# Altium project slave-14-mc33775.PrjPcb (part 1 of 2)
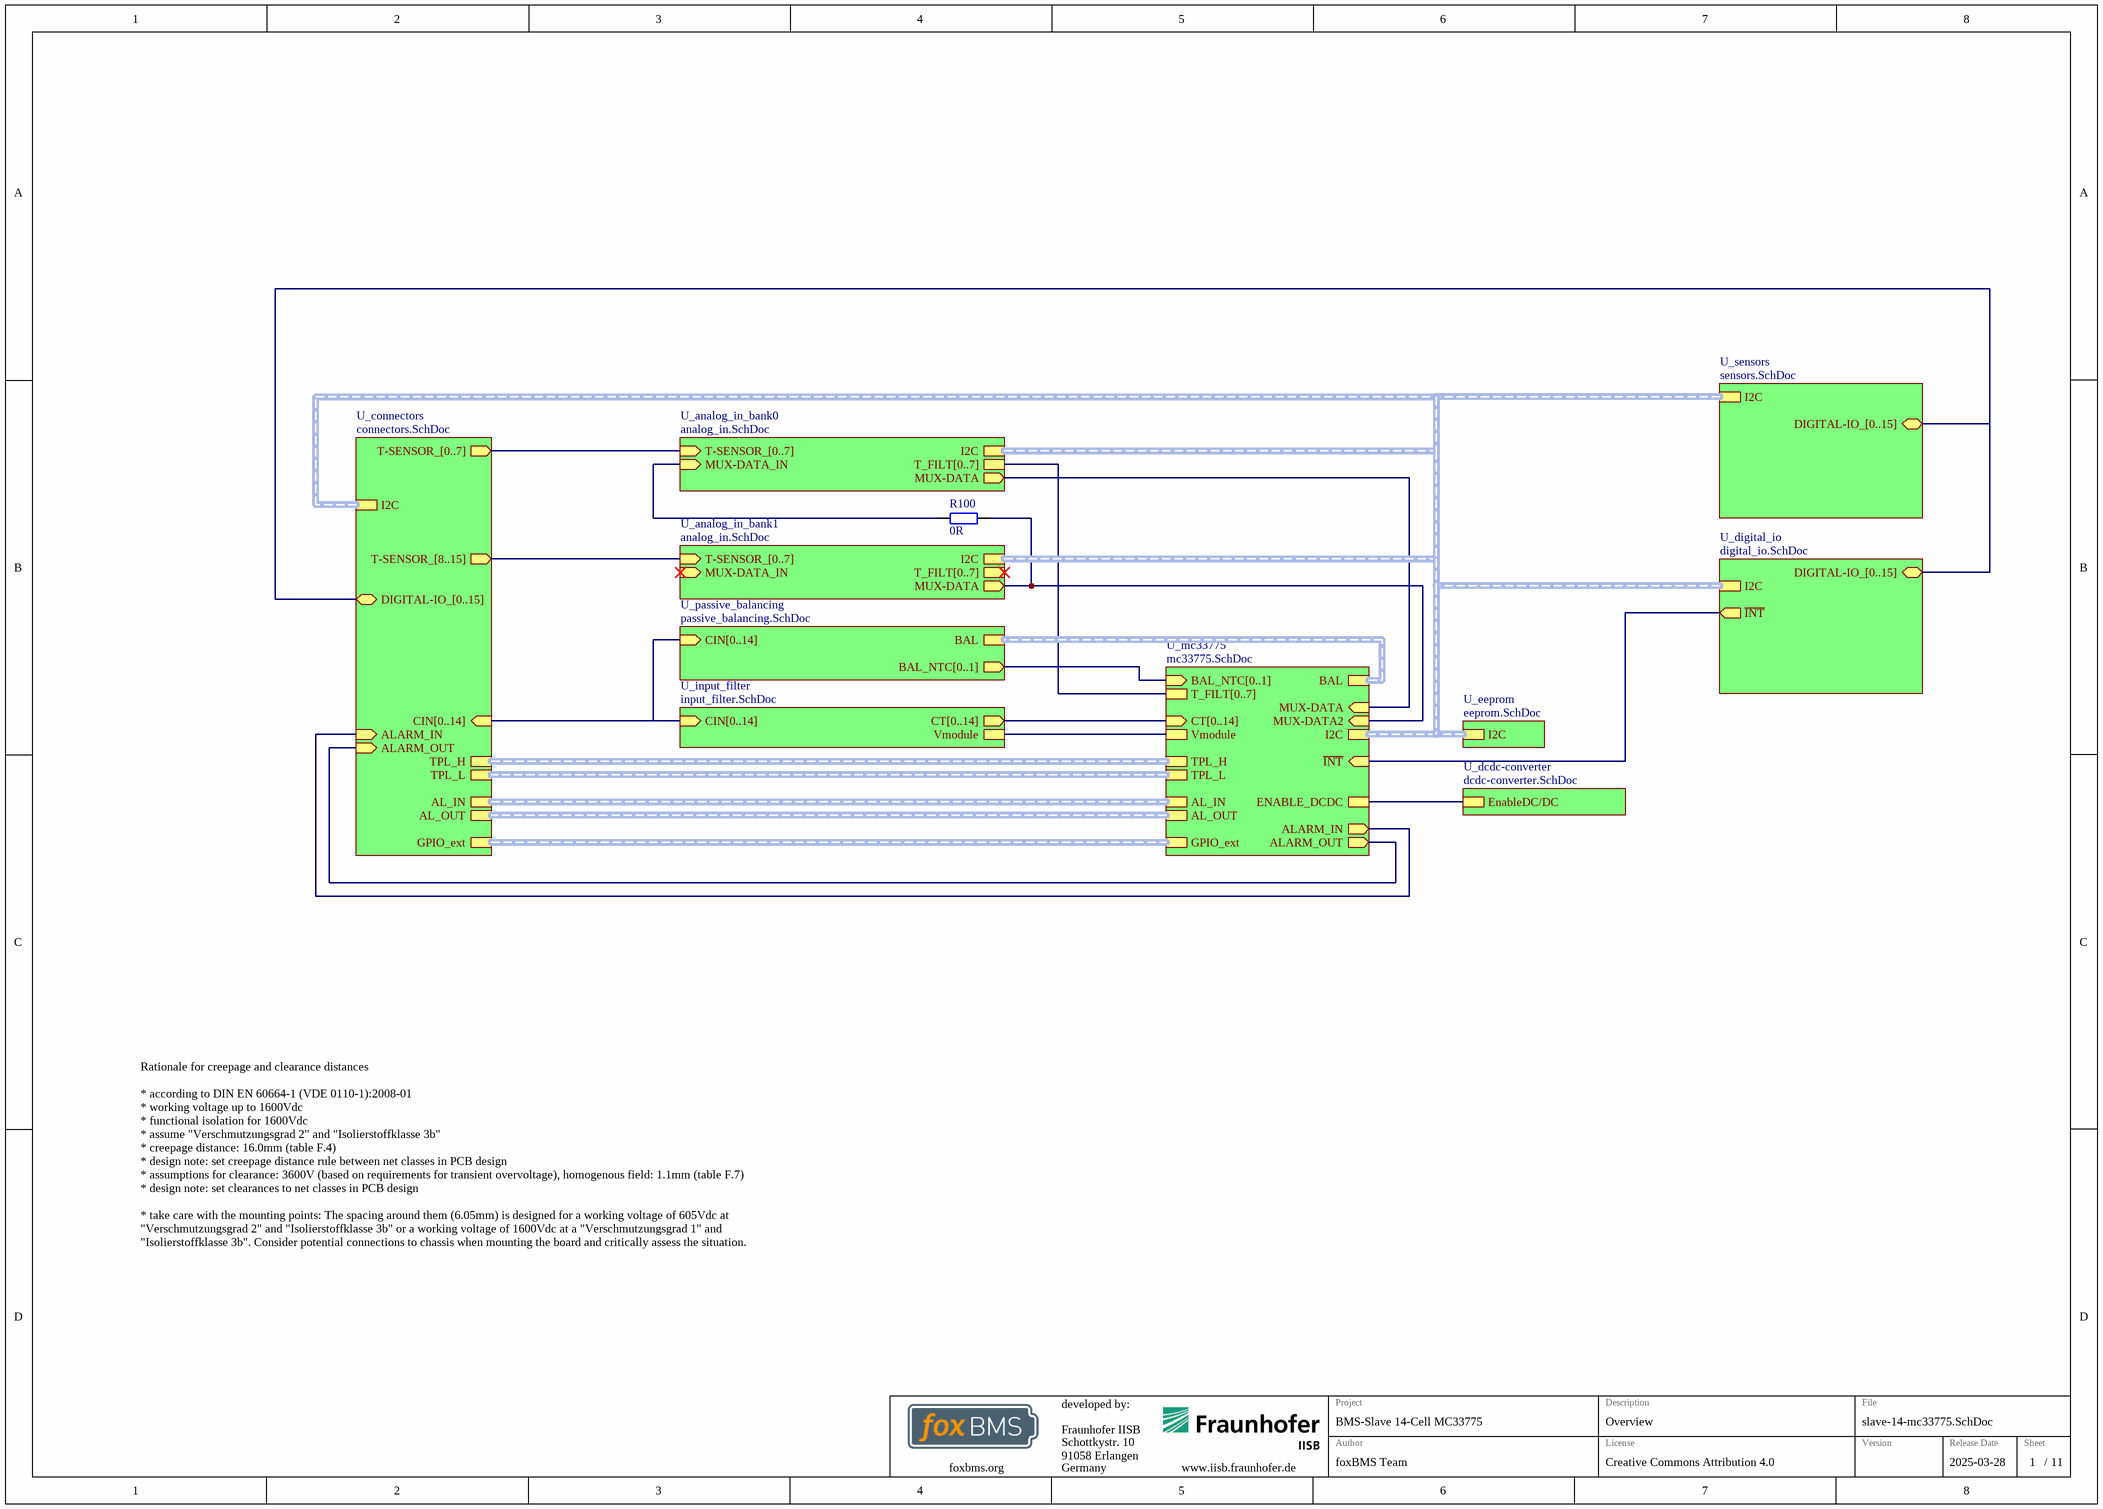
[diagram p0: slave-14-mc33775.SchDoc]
Global_Suffix_Version: 0; Global_Major_Minor_Patch_Version: 1.0.3; GlobalVersion: ='v'+Global_Major_Minor_Patch_Version+'-'+Global_Suffix_Version; GlobalStatus: A; GlobalProject: BMS-Slave 14-Cell MC33775; GlobalLicense: Creative Commons Attribution 4.0; GlobalDate: 2025-03-28; GlobalAuthor: foxBMS Team
11 sheets, 421 parts. Net scope: hierarchical (ports join the sheet entries above them; power ports are global).
Board file: slave-14-mc33775.PcbDoc
Sheets:
  slave-14-mc33775.SchDoc
    U_mc33775 = mc33775.SchDoc
      U_ldo = ldo.SchDoc
    U_eeprom = eeprom.SchDoc
    U_input_filter = input_filter.SchDoc
    U_passive_balancing = passive_balancing.SchDoc
    U_analog_in_bank0 = analog_in.SchDoc
    U_connectors = connectors.SchDoc
    U_dcdc-converter = dcdc-converter.SchDoc
    U_sensors = sensors.SchDoc
    U_digital_io = digital_io.SchDoc
    U_analog_in_bank1 = analog_in.SchDoc

## Sheet slave-14-mc33775.SchDoc
size A3; DocumentNumber: 1; SheetNumber: 1; SheetTotal: 11; SheetDescription: Overview

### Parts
R100  0R  [RESC1608X05N]

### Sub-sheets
U_analog_in_bank0 = analog_in.SchDoc: MUX-DATA (out), T-SENSOR_[0..7] (in), I2C (harness I2C), MUX-DATA_IN (in), T_FILT[0..7]
U_analog_in_bank1 = analog_in.SchDoc: MUX-DATA (out), T-SENSOR_[0..7] (in), I2C (harness I2C), MUX-DATA_IN (in), T_FILT[0..7]
U_connectors = connectors.SchDoc: T-SENSOR_[0..7] (out), CIN[0..14] (in), TPL_L (harness TPL), TPL_H (harness TPL), AL_OUT (harness ALARM), AL_IN (harness ALARM), GPIO_ext (harness GPIO_ext), T-SENSOR_[8..15] (out), DIGITAL-IO_[0..15] (bidir), ALARM_IN (in), ALARM_OUT (in), I2C (harness I2C)
U_dcdc-converter = dcdc-converter.SchDoc: EnableDC/DC
U_digital_io = digital_io.SchDoc: DIGITAL-IO_[0..15] (bidir), ~{INT} (out), I2C (harness I2C)
U_eeprom = eeprom.SchDoc: I2C (harness I2C)
U_input_filter = input_filter.SchDoc: CT[0..14] (out), CIN[0..14] (in), Vmodule
U_mc33775 = mc33775.SchDoc: I2C (harness I2C), CT[0..14] (in), BAL (harness BAL), AL_IN (harness ALARM), AL_OUT (harness ALARM), BAL_NTC[0..1] (in), MUX-DATA (in), TPL_L (harness TPL), TPL_H (harness TPL), GPIO_ext (harness GPIO_ext), MUX-DATA2 (in), ~{INT} (in), T_FILT[0..7], ENABLE_DCDC, ALARM_IN (out), ALARM_OUT (out), Vmodule
U_passive_balancing = passive_balancing.SchDoc: CIN[0..14] (in), BAL (harness BAL), BAL_NTC[0..1] (out)
U_sensors = sensors.SchDoc: DIGITAL-IO_[0..15] (bidir), I2C (harness I2C)

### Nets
VMODULE: sheet U_mc33775/Vmodule, sheet U_input_filter/Vmodule
ALARM_IN: sheet U_mc33775/ALARM_IN, sheet U_connectors/ALARM_IN
ALARM_OUT: sheet U_mc33775/ALARM_OUT, sheet U_connectors/ALARM_OUT
INT: sheet U_mc33775/~{INT}, sheet U_digital_io/~{INT}
MUX-DATA_IN: R100.1 ; sheet U_analog_in_bank0/MUX-DATA_IN
MUX_DATA: sheet U_mc33775/MUX-DATA, sheet U_analog_in_bank0/MUX-DATA
MUX_DATA2: R100.2 ; sheet U_mc33775/MUX-DATA2, sheet U_analog_in_bank1/MUX-DATA
NetR601_2: sheet U_mc33775/ENABLE_DCDC, sheet U_dcdc-converter/EnableDC/DC

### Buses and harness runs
bus sheet U_analog_in_bank0/T-SENSOR_[0..7] = sheet U_connectors/T-SENSOR_[0..7]
bus sheet U_analog_in_bank0/T_FILT[0..7] = sheet U_mc33775/T_FILT[0..7]
bus sheet U_analog_in_bank1/T-SENSOR_[0..7] = sheet U_connectors/T-SENSOR_[8..15]
bus sheet U_connectors/CIN[0..14] = sheet U_input_filter/CIN[0..14] = sheet U_passive_balancing/CIN[0..14]
bus sheet U_connectors/DIGITAL-IO_[0..15] = sheet U_digital_io/DIGITAL-IO_[0..15] = sheet U_sensors/DIGITAL-IO_[0..15]
bus sheet U_input_filter/CT[0..14] = sheet U_mc33775/CT[0..14]
bus sheet U_mc33775/BAL_NTC[0..1] = sheet U_passive_balancing/BAL_NTC[0..1]
harness sheet U_analog_in_bank0/I2C = sheet U_analog_in_bank1/I2C = sheet U_connectors/I2C = sheet U_digital_io/I2C = sheet U_eeprom/I2C = sheet U_mc33775/I2C = sheet U_sensors/I2C
harness sheet U_connectors/AL_IN = sheet U_mc33775/AL_IN
harness sheet U_connectors/AL_OUT = sheet U_mc33775/AL_OUT
harness sheet U_connectors/GPIO_ext = sheet U_mc33775/GPIO_ext
harness sheet U_connectors/TPL_H = sheet U_mc33775/TPL_H
harness sheet U_connectors/TPL_L = sheet U_mc33775/TPL_L
harness sheet U_mc33775/BAL = sheet U_passive_balancing/BAL

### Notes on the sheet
- Rationale for creepage and clearance distances
  * according to DIN EN 60664-1 (VDE 0110-1):2008-01
  * working voltage up to 1600Vdc
  * functional isolation for 1600Vdc
  * assume "Verschmutzungsgrad 2" and "Isolierstoffklasse 3b"
  * creepage distance: 16.0mm (table F.4)
  * design note: set creepage distance rule between net classes in PCB design
  * assumptions for clearance: 3600V (based on requirements for transient overvoltage), homogenous field: 1.1mm (table F.7)
  * design note: set clearances to net classes in PCB design
  * take care with the mounting points: The spacing around them (6.05mm) is designed for a working voltage of 605Vdc at "Verschmutzungsgrad 2" and "Isolierstoffklasse 3b" or a working voltage of 1600Vdc at a "Verschmutzungsgrad 1" and "Isolierstoffklasse 3b". Consider potential connections to chassis when mounting the board and critically assess the situation.

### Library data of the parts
R100 = gen_R_0R_0603: SMD Resistor 0R 0603; Power: 0.1W; Case EIA: 0603; Case Metric: 1608; Maximum Working Voltage: 75V; PnP Package: 0603R; Automotive Qualified: True; PnP equipped: x

## Sheet mc33775.SchDoc
size A3; DocumentNumber: 2; SheetNumber: 2; SheetTotal: 11; SheetDescription: MC33775A BMS IC
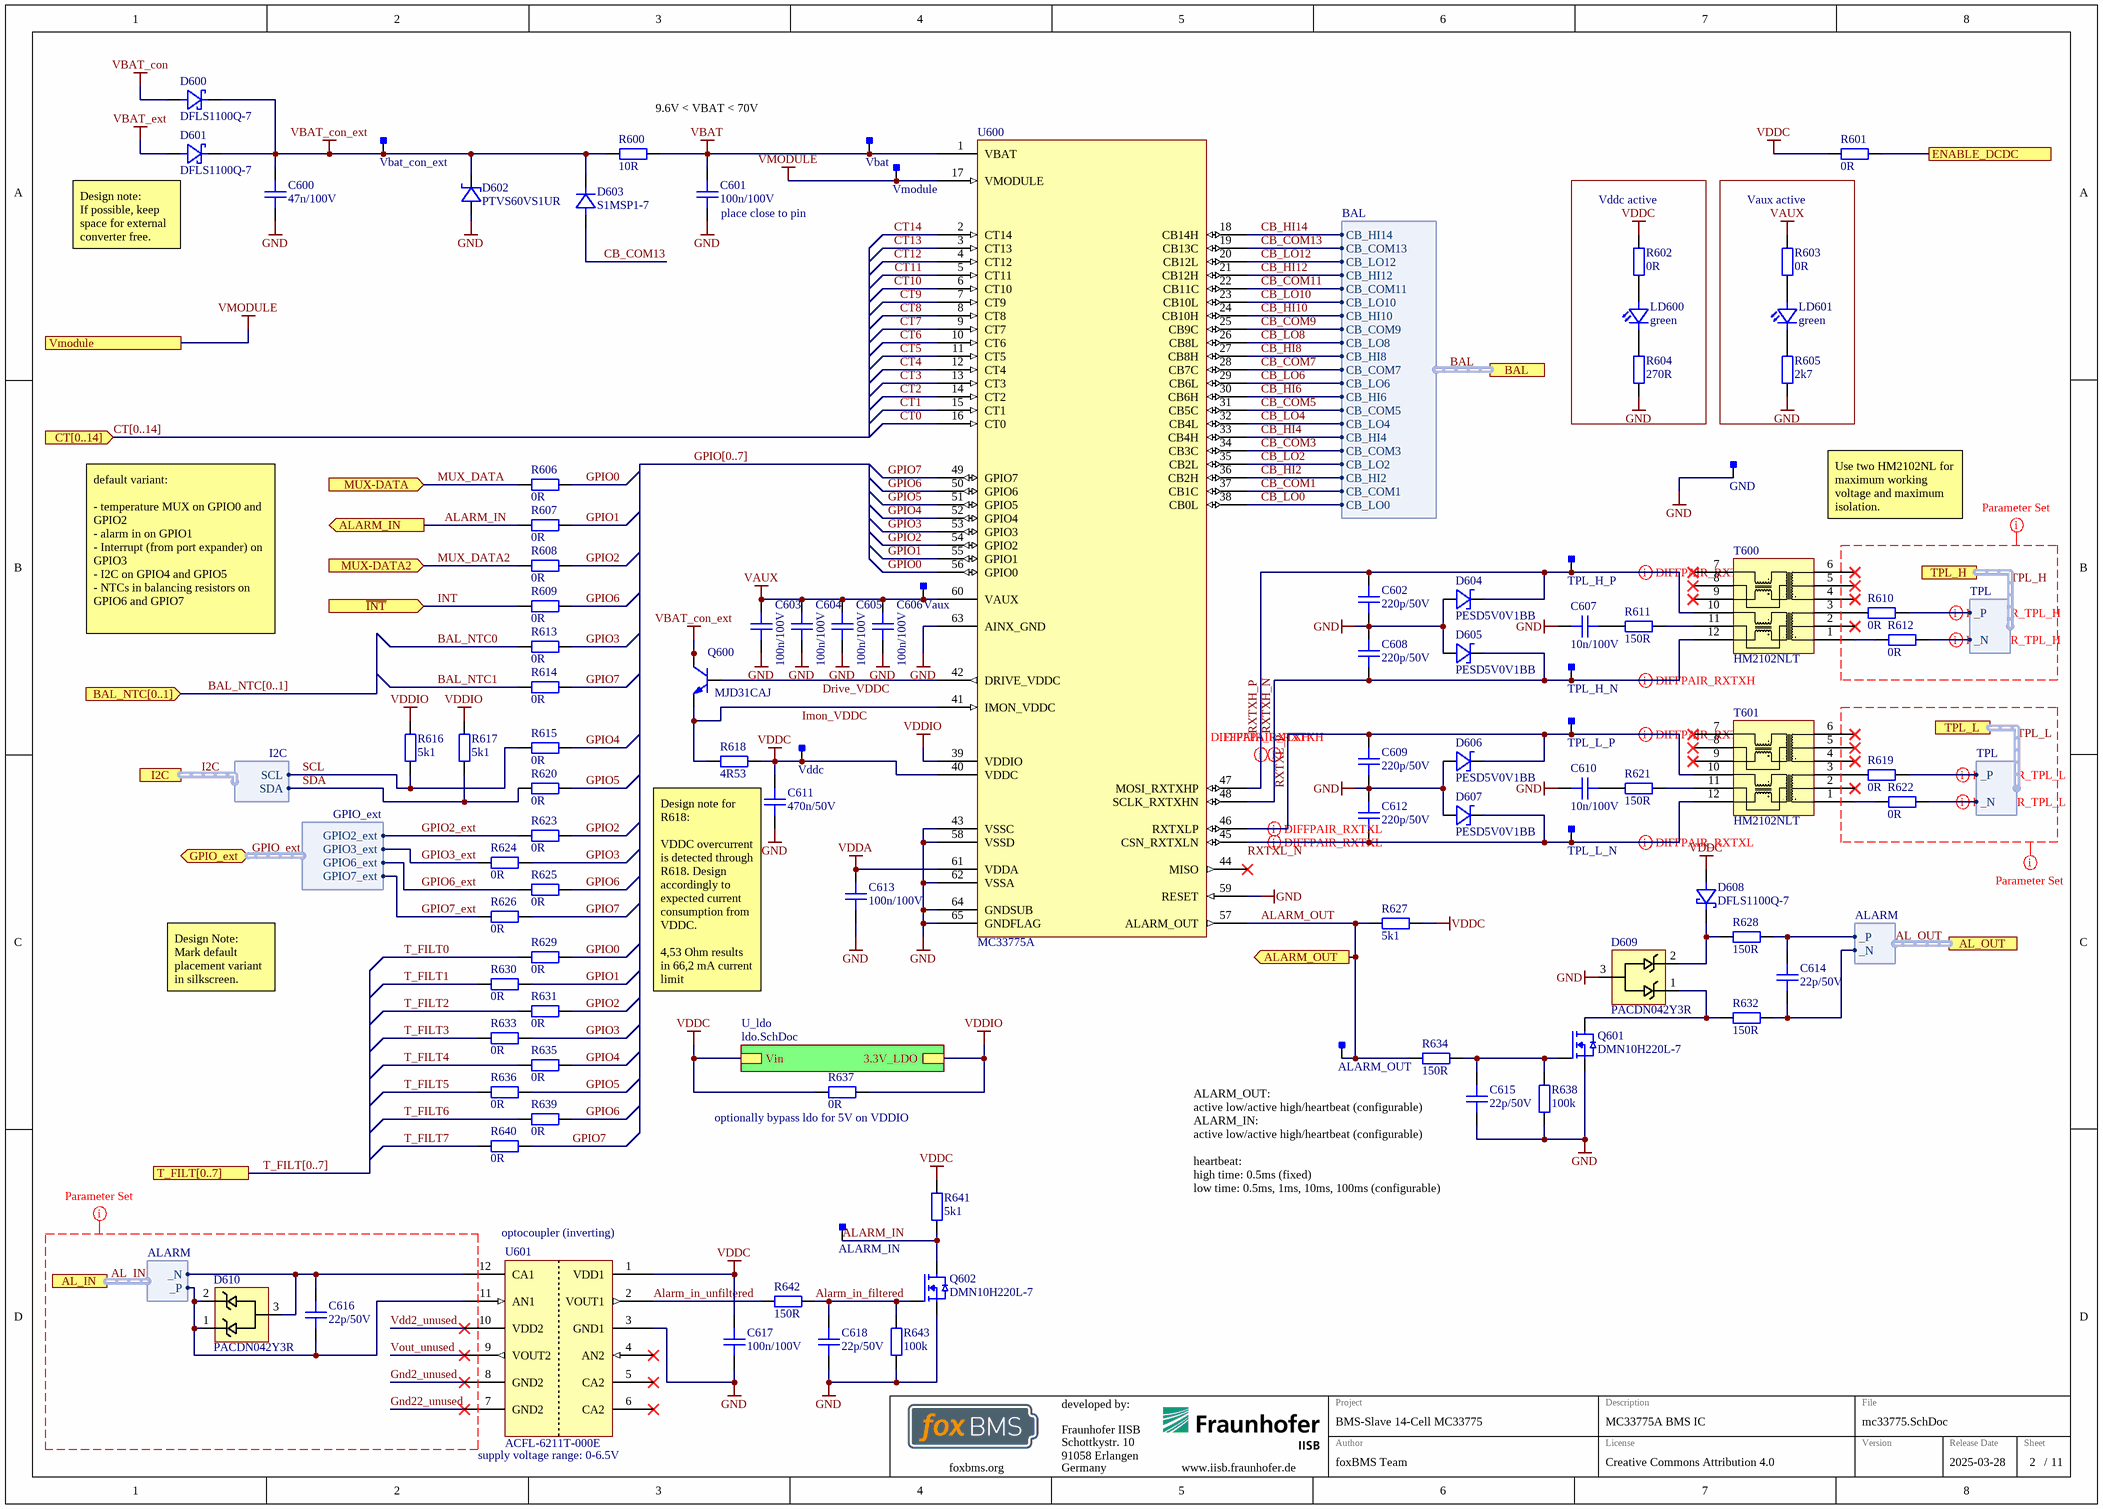
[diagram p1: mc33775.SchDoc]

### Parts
ALARM_IN  Testpoint_Square  [Testpoint_S1]  (value not drawn)  (no BOM)
ALARM_OUT  Testpoint_Square  [Testpoint_S1]  (value not drawn)  (no BOM)
C600  47n/100V  [CAPC1608X08N]
C601  100n/100V  [CAPC1608X08N]
C602  220p/50V  [CAPC1608X08N]
C603  100n/100V  [CAPC1608X08N]
C604  100n/100V  [CAPC1608X08N]
C605  100n/100V  [CAPC1608X08N]
C606  100n/100V  [CAPC1608X08N]
C607  10n/100V  [CAPC1608X08N]
C608  220p/50V  [CAPC1608X08N]
C609  220p/50V  [CAPC1608X08N]
C610  10n/100V  [CAPC1608X08N]
C611  470n/50V  [CAPC1608X08N]
C612  220p/50V  [CAPC1608X08N]
C613  100n/100V  [CAPC1608X08N]
C614  22p/50V  [CAPC1005X06N]
C615  22p/50V  [CAPC1005X06N]
C616  22p/50V  [CAPC1005X06N]
C617  100n/100V  [CAPC1608X08N]
C618  22p/50V  [CAPC1005X06N]
D600  DFLS1100Q-7  [PowerDI123]
D601  DFLS1100Q-7  [PowerDI123]
D602  PTVS60VS1UR  [NEXPERIA_PTVSxS1UR]
D603  S1MSP1-7  [S1MSP1]
D604  PESD5V0V1BB  [SOD523_PESD_NEXPERIA]
D605  PESD5V0V1BB  [SOD523_PESD_NEXPERIA]
D606  PESD5V0V1BB  [SOD523_PESD_NEXPERIA]
D607  PESD5V0V1BB  [SOD523_PESD_NEXPERIA]
D608  DFLS1100Q-7  [PowerDI123]
D609  PACDN042Y3R  [ON-SEMI-SOT-23-3-CASE-318-08]
D610  PACDN042Y3R  [ON-SEMI-SOT-23-3-CASE-318-08]
GND  Testpoint_Square  [Testpoint_S1]  (value not drawn)  (no BOM)
LD600  green  [LEDC1608X07N]
LD601  green  [LEDC1608X07N]
Q600  MJD31CAJ  [NEXPERIA_DPAK_SOT428C]
Q601  DMN10H220L-7  [SOT95P237X110-3N]
Q602  DMN10H220L-7  [SOT95P237X110-3N]
R600  10R  [RESC2012X05N]
R601  0R  [RESC1608X05N]
R602  0R  [RESC1608X05N]
R603  0R  [RESC1608X05N]
R604  270R  [RESC1608X05N]
R605  2k7  [RESC1608X05N]
R606  0R  [RESC1608X05N]
R607  0R  [RESC1608X05N]
R608  0R  [RESC1608X05N]
R609  0R  [RESC1608X05N]
R610  0R  [RESC1608X05N]
R611  150R  [RESC1608X05N]
R612  0R  [RESC1608X05N]
R613  0R  [RESC1608X05N]
R614  0R  [RESC1608X05N]
R615  0R  [RESC1608X05N]
R616  5k1  [RESC1608X05N]
R617  5k1  [RESC1608X05N]
R618  4R53  [RESC1608X05N]
R619  0R  [RESC1608X05N]
R620  0R  [RESC1608X05N]
R621  150R  [RESC1608X05N]
R622  0R  [RESC1608X05N]
R623  0R  [RESC1608X05N]
R624  0R  [RESC1608X05N]
R625  0R  [RESC1608X05N]
R626  0R  [RESC1608X05N]
R627  5k1  [RESC1608X05N]
R628  150R  [RESC1608X05N]
R629  0R  [RESC1608X05N]
R630  0R  [RESC1608X05N]
R631  0R  [RESC1608X05N]
R632  150R  [RESC1608X05N]
R633  0R  [RESC1608X05N]
R634  150R  [RESC1608X05N]
R635  0R  [RESC1608X05N]
R636  0R  [RESC1608X05N]
R637  0R  [RESC1608X05N]
R638  100k  [RESC1608X05N]
R639  0R  [RESC1608X05N]
R640  0R  [RESC1608X05N]
R641  5k1  [RESC1608X05N]
R642  150R  [RESC1608X05N]
R643  100k  [RESC1608X05N]
T600  HM2102NLT  [HM2102NL]
T601  HM2102NLT  [HM2102NL]
TPL_H_N  Testpoint_Square  [Testpoint_S1]  (value not drawn)  (no BOM)
TPL_H_P  Testpoint_Square  [Testpoint_S1]  (value not drawn)  (no BOM)
TPL_L_N  Testpoint_Square  [Testpoint_S1]  (value not drawn)  (no BOM)
TPL_L_P  Testpoint_Square  [Testpoint_S1]  (value not drawn)  (no BOM)
U600  MC33775A  [NXP_SOT1510-2]
U601  ACFL-6211T-000E  [Broadcom_ACFL-6211T]
Vaux  Testpoint_Square  [Testpoint_S1]  (value not drawn)  (no BOM)
Vbat  Testpoint_Square  [Testpoint_S1]  (value not drawn)  (no BOM)
Vbat_con_ext  Testpoint_Square  [Testpoint_S1]  (value not drawn)  (no BOM)
Vddc  Testpoint_Square  [Testpoint_S1]  (value not drawn)  (no BOM)
Vmodule  Testpoint_Square  [Testpoint_S1]  (value not drawn)  (no BOM)

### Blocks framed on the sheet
Vddc active: LD600 R602 R604
Vaux active: LD601 R603 R605

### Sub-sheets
U_ldo = ldo.SchDoc: 3.3V_LDO, Vin

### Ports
AL_IN (harness ALARM), AL_OUT (harness ALARM), ALARM_IN (out), ALARM_OUT (out), BAL (harness BAL), BAL_NTC[0..1] (in), CT[0..14] (in), ENABLE_DCDC, GPIO_ext (bidir, harness GPIO_ext), I2C (harness I2C), MUX-DATA2 (in), MUX-DATA (in), T_FILT[0..7], TPL_H (harness TPL), TPL_L (harness TPL), Vmodule, ~{INT} (in)

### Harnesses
BAL: CB_HI14, CB_COM13, CB_LO12, CB_HI12, CB_COM11, CB_LO10, CB_HI10, CB_COM9, CB_LO8, CB_HI8, CB_COM7, CB_LO6, CB_HI6, CB_COM5, CB_LO4, CB_HI4, CB_COM3, CB_LO2, CB_HI2, CB_COM1, CB_LO0
TPL: _P, _N
ALARM: _P, _N
I2C: SCL, SDA
GPIO_ext: GPIO3_ext, GPIO2_ext, GPIO6_ext, GPIO7_ext

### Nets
GND: C600.1 C601.1 C602.1 C603.1 C604.1 C605.1 C606.1 C607.1 C608.2 C609.1 C610.1 C611.1 C612.2 C613.1 C615.1 C617.1 C618.1 D602.2(A) D604.2(A) D605.2(A) D606.2(A) D607.2(A) D609.3 GND.1 Q601.S Q602.S R604.1 R605.1 R638.2 R643.2 U600.43(VSSC) U600.58(VSSD) U600.59(RESET) U600.62(VSSA) U600.63(AINX_GND) U600.64(GNDSUB) U600.65(GNDFLAG) U601.3(GND1)
VAUX: C603.2 C604.2 C605.2 C606.2 R603.2 U600.60(VAUX) Vaux.1
VBAT: C601.2 R600.1 U600.1(VBAT) Vbat.1
VBAT_con: D600.2(A)
VBAT_con_ext: C600.2 D600.1(K) D601.1(K) D602.1(C) D603.1(K) Q600.2(C) Q600.4(C) R600.2 Vbat_con_ext.1
VBAT_ext: D601.2(A)
VDDA: C613.2 U600.61(VDDA)
VDDC: C611.2 C617.2 D608.2(A) R601.1 R602.2 R618.2 R627.1 R637.2 R641.1 U600.40(VDDC) U601.1(VDD1) Vddc.1 ; sheet U_ldo/Vin
VDDIO: R616.2 R617.2 R637.1 U600.39(VDDIO) ; sheet U_ldo/3.3V_LDO
VMODULE: U600.17(VMODULE) Vmodule.1 ; port Vmodule
AL_IN._N: C616.2 D610.3 U601.12(CA1) ; port AL_IN._N
AL_IN._P: C616.1 D610.1 D610.2 U601.11(AN1) ; port AL_IN._P
AL_OUT._N: C614.1 R632.2 ; port AL_OUT._N
AL_OUT._P: C614.2 R628.2 ; port AL_OUT._P
ALARM_IN: ALARM_IN.1 Q602.D R607.1 R641.2 ; port ALARM_IN
Alarm_in_filtered: C618.2 Q602.G R642.2 R643.1
Alarm_in_unfiltered: R642.1 U601.2(VOUT1)
ALARM_OUT: ALARM_OUT.1 R627.2 R634.1 U600.57(ALARM_OUT) ; port ALARM_OUT
BAL_NTC0: R613.1
BAL_NTC1: R614.1
CB_COM1: U600.37(CB1C) ; port BAL.CB_COM1  [project net BAL.CB_COM1]
CB_COM3: U600.34(CB3C) ; port BAL.CB_COM3  [project net BAL.CB_COM3]
CB_COM5: U600.31(CB5C) ; port BAL.CB_COM5  [project net BAL.CB_COM5]
CB_COM7: U600.28(CB7C) ; port BAL.CB_COM7  [project net BAL.CB_COM7]
CB_COM9: U600.25(CB9C) ; port BAL.CB_COM9  [project net BAL.CB_COM9]
CB_COM11: U600.22(CB11C) ; port BAL.CB_COM11  [project net BAL.CB_COM11]
CB_COM13: D603.2(A) U600.19(CB13C) ; port BAL.CB_COM13  [project net BAL.CB_COM13]
CB_HI2: U600.36(CB2H) ; port BAL.CB_HI2  [project net BAL.CB_HI2]
CB_HI4: U600.33(CB4H) ; port BAL.CB_HI4  [project net BAL.CB_HI4]
CB_HI6: U600.30(CB6H) ; port BAL.CB_HI6  [project net BAL.CB_HI6]
CB_HI8: U600.27(CB8H) ; port BAL.CB_HI8  [project net BAL.CB_HI8]
CB_HI10: U600.24(CB10H) ; port BAL.CB_HI10  [project net BAL.CB_HI10]
CB_HI12: U600.21(CB12H) ; port BAL.CB_HI12  [project net BAL.CB_HI12]
CB_HI14: U600.18(CB14H) ; port BAL.CB_HI14  [project net BAL.CB_HI14]
CB_LO0: U600.38(CB0L) ; port BAL.CB_LO0  [project net BAL.CB_LO0]
CB_LO2: U600.35(CB2L) ; port BAL.CB_LO2  [project net BAL.CB_LO2]
CB_LO4: U600.32(CB4L) ; port BAL.CB_LO4  [project net BAL.CB_LO4]
CB_LO6: U600.29(CB6L) ; port BAL.CB_LO6  [project net BAL.CB_LO6]
CB_LO8: U600.26(CB8L) ; port BAL.CB_LO8  [project net BAL.CB_LO8]
CB_LO10: U600.23(CB10L) ; port BAL.CB_LO10  [project net BAL.CB_LO10]
CB_LO12: U600.20(CB12L) ; port BAL.CB_LO12  [project net BAL.CB_LO12]
CT0: U600.16(CT0)
CT1: U600.15(CT1)
CT2: U600.14(CT2)
CT3: U600.13(CT3)
CT4: U600.12(CT4)
CT5: U600.11(CT5)
CT6: U600.10(CT6)
CT7: U600.9(CT7)
CT8: U600.8(CT8)
CT9: U600.7(CT9)
CT10: U600.6(CT10)
CT11: U600.5(CT11)
CT12: U600.4(CT12)
CT13: U600.3(CT13)
CT14: U600.2(CT14)
Drive_VDDC: Q600.1(B) U600.42(DRIVE_VDDC)
Gnd2_unused: U601.8(GND2)
Gnd22_unused: U601.7(GND2)
GPIO0: R606.2 R629.2 U600.56(GPIO0)
GPIO1: R607.2 R630.2 U600.55(GPIO1)
GPIO2: R608.2 R623.2 R631.2 U600.54(GPIO2)
GPIO2_ext: R623.1 ; port GPIO_ext.GPIO2_ext
GPIO3: R613.2 R624.2 R633.2 U600.53(GPIO3)
GPIO3_ext: R624.1 ; port GPIO_ext.GPIO3_ext
GPIO4: R615.2 R635.2 U600.52(GPIO4)
GPIO5: R620.2 R636.2 U600.51(GPIO5)
GPIO6: R609.2 R625.2 R639.2 U600.50(GPIO6)
GPIO6_ext: R625.1 ; port GPIO_ext.GPIO6_ext
GPIO7: R614.2 R626.2 R640.2 U600.49(GPIO7)
GPIO7_ext: R626.1 ; port GPIO_ext.GPIO7_ext
Imon_VDDC: Q600.3(E) R618.1 U600.41(IMON_VDDC)
INT: R609.1 ; port ~{INT}
MUX_DATA: R606.1 ; port MUX-DATA
MUX_DATA2: R608.1 ; port MUX-DATA2
RXTXH_N: C608.1 D605.1(C) T600.12 TPL_H_N.1 U600.48(SCLK_RXTXHN)
RXTXH_P: C602.2 D604.1(C) T600.10 TPL_H_P.1 U600.47(MOSI_RXTXHP)
RXTXL_N: C612.1 D607.1(C) T601.12 TPL_L_N.1 U600.45(CSN_RXTXLN)
RXTXL_P: C609.2 D606.1(C) T601.10 TPL_L_P.1 U600.46(RXTXLP)
SCL: R615.1 R616.1 ; port I2C.SCL  [project net I2C.SCL]
SDA: R617.1 R620.1 ; port I2C.SDA  [project net I2C.SDA]
T_FILT0: R629.1
T_FILT1: R630.1
T_FILT2: R631.1
T_FILT3: R633.1
T_FILT4: R635.1
T_FILT5: R636.1
T_FILT6: R639.1
T_FILT7: R640.1
TPL_H._N: R612.2 ; port TPL_H._N
TPL_H._P: R610.2 ; port TPL_H._P
TPL_L._N: R622.2 ; port TPL_L._N
TPL_L._P: R619.2 ; port TPL_L._P
Vdd2_unused: U601.10(VDD2)
Vout_unused: U601.9(VOUT2)
NetC607_2: C607.2 R611.1
NetC610_2: C610.2 R621.1
NetC615_2: C615.2 Q601.G R634.2 R638.1
NetD608_1: D608.1(K) D609.2 R628.1
NetD609_1: D609.1 Q601.D R632.1
NetLD600_1: LD600.1(C) R604.2
NetLD600_2: LD600.2(A) R602.1
NetLD601_1: LD601.1(C) R605.2
NetLD601_2: LD601.2(A) R603.1
NetR601_2: R601.2 ; port ENABLE_DCDC
NetR610_1: R610.1 T600.3
NetR611_2: R611.2 T600.11
NetR612_1: R612.1 T600.1
NetR619_1: R619.1 T601.3
NetR621_2: R621.2 T601.11
NetR622_1: R622.1 T601.1

Not connected (* = marked no-connect by the designer): T600 2* 4* 5* 6* 7* 8* 9*; T601 2* 4* 5* 6* 7* 8* 9*; U600 44(MISO)*; U601 4(AN2)* 5(CA2)* 6(CA2)*

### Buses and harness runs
bus BAL_NTC[0..1] = port BAL_NTC[0..1]
bus CT[0..14] = port CT[0..14]
bus GPIO[0..7]
bus T_FILT[0..7] = port T_FILT[0..7]
harness AL_IN = port AL_IN
harness AL_OUT = port AL_OUT
harness BAL = port BAL
harness GPIO_ext = port GPIO_ext
harness I2C = port I2C
harness TPL_H = port TPL_H
harness TPL_L = port TPL_L

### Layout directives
differential pair: RXTXH_N, RXTXH_P, RXTXL_N, RXTXL_P, TPL_L._N, TPL_L._P
differential pair; differential pair class TPL_H: TPL_H._N, TPL_H._P
net class TPL_high: TPL_H
net class TPL_low: TPL_L
net class ALARM_in: AL_IN, Gnd2_unused, Gnd22_unused, Vdd2_unused, Vout_unused

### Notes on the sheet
- (near R600) 9.6V < VBAT < 70V
- (near D601) Design note:
  If possible, keep space for external converter free.
- (near C601) place close to pin
- Use two HM2102NL for maximum working voltage and maximum isolation.
- default variant:
  - temperature MUX on GPIO0 and GPIO2
  - alarm in on GPIO1
  - Interrupt (from port expander) on GPIO3
  - I2C on GPIO4 and GPIO5
  - NTCs in balancing resistors on GPIO6 and GPIO7
- Design Note:
  Mark default placement variant in silkscreen.
- (near C611) Design note for R618:
  VDDC overcurrent is detected through R618. Design accordingly to expected current consumption from VDDC.
  4,53 Ohm results in 66,2 mA current limit
- (near R637) optionally bypass ldo for 5V on VDDIO
- ALARM_OUT:
  active low/active high/heartbeat (configurable)
  ALARM_IN:
  active low/active high/heartbeat (configurable)
  heartbeat:
  high time: 0.5ms (fixed)
  low time: 0.5ms, 1ms, 10ms, 100ms (configurable)
- (near U601) optocoupler (inverting)
- (near U601) supply voltage range: 0-6.5V

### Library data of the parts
ALARM_IN ALARM_OUT GND TPL_H_N TPL_H_P TPL_L_N TPL_L_P Vaux Vbat Vbat_con_ext Vddc Vmodule = Testpoint_Square: Testpoint, square; Automotive Qualified: False
C600 = gen_C_ceramic_47n_100V_X7R_0603: MLCC; Capacitance: 47n; Rated Voltage: 100V; Dielectric: X7R; Case EIA: 0603; Case Metric: 1608; Automotive Qualified: True; PnP Package: 0603C
C601 C603-C606 C613 C617 = gen_C_ceramic_100n_100V_X7R_0603: MLCC; Capacitance: 100n; Rated Voltage: 100V; Dielectric: X7R; Case EIA: 0603; Case Metric: 1608; Automotive Qualified: True; PnP Package: 0603C
C602 C608 C609 C612 = gen_C_ceramic_220p_50V_C0G_0603: MLCC; Capacitance: 220p; Rated Voltage: 50V; Dielectric: C0G; Case EIA: 0603; Case Metric: 1608; Automotive Qualified: True; AEC-Q Norm: AEC-Q200; PnP Package: 0603C
C607 C610 = gen_C_ceramic_10n_100V_X7R_0603: MLCC; Capacitance: 10n; Rated Voltage: 100V; Dielectric: X7R; Case EIA: 0603; Case Metric: 1608; PnP Package: 0603C; PnP Value: 10nF/100V/X7R; Automotive Qualified: True; AEC-Q Norm: AEC-Q200
C611 = gen_C_ceramic_470n_50V_X7R_0603: MLCC; Capacitance: 470n; Rated Voltage: 50V; Dielectric: X7R; Case EIA: 0603; Case Metric: 1608; Automotive Qualified: True; AEC-Q Norm: AEC-Q200; PnP Package: 0603C
C614-C616 C618 = gen_C_ceramic_22p_50V_C0G_0402: MLCC; Capacitance: 22p; Rated Voltage: 50V; Dielectric: C0G; Case EIA: 0402; Case Metric: 1005; PnP Package: 0402C; Automotive Qualified: True; Tolerance: 1%
D600 D601 D608 = DFLS1100Q-7: Schottky Diode; Manufacturer: Diodes Inc.; Breakdown Voltage: 100V; Continuous Forward Current: 1A; Automotive Qualified: True
D602 = PTVS60VS1UR: 400W Transient Voltage Suppressor; Part Name: PTVSxS1UR; Manufacturer: Nexperia; Breakdown Voltage: 70.20V; Automotive Qualified: True; AEC-Q Norm: AEC-Q101
D603 = S1MSP1-7: 1.0A surface mount glass passivated rectifier; Manufacturer: Diodes Inc.; Breakdown Voltage: 1000V; Continuous Forward Current: 1A; Automotive Qualified: False
D604-D607 = PESD5V0V1BB: Very low capacitance bidirectional ESD protection diode; Manufacturer: Nexperia; Breakdown Voltage: 6.8V; PnP Package: SOD523; Automotive Qualified: True; AEC-Q Norm: AEC-Q101
D609 D610 = PACDN042Y3R: ESD-Schutzbaustein; Manufacturer: ON Semiconductor; Breakdown Voltage: 8V; PnP Package: SOT23-3; Automotive Qualified: True
LD600 LD601 = LED_0603_green_AECQ: TLMG1100-GS08; Manufacturer: Vishay; Breakdown Voltage: 5V; Continuous Forward Current: 20mA; Forward Voltage @ 20mA: 2.1V; Automotive Qualified: True
Q600 = MJD31CAJ: 100V, 3A NPN high power bipolar transistor; Manufacturer: Nexperia; Automotive Qualified: True; AEC-Q Norm: AEC-Q101
Q601 Q602 = DMN10H220L-7: MOSFET-Transistor, n-Kanal, 1.6 A, 100 V, 0.250 ohm; Manufacturer: Diodes; Maximum Drain-Source Voltage: 100V; Maximum Continous Drain Current (25°C): 1.6A; R_DS(on): 250m; Total Gate Charge: 4.1nC; Automotive Qualified: True
R600 = gen_R_10R_0805: SMD Resistor 10R 0805; Tolerance: 1%; Power: 0.125W; Case EIA: 0805; Case Metric: 2012; Maximum Working Voltage: 150V; PnP Package: 0805R; Automotive Qualified: True; AEC-Q Norm: AEC-Q200; AEC-Q Grade: Grade 0
R601-R603 R606-R610 R612-R615 R619 R620 R622-R626 R629-R631 R633 R635-R637 R639 R640 = gen_R_0R_0603: as R100 on sheet slave-14-mc33775
R604 = gen_R_270R_0603: SMD Resistor 270R 0603; Tolerance: 1%; Power: 0.1W; Case EIA: 0603; Case Metric: 1608; Maximum Working Voltage: 75V; PnP Package: 0603R; Automotive Qualified: True
R605 = gen_R_2k7_0603: SMD Resistor 2k7 0603; Tolerance: 1%; Power: 0.1W; Case EIA: 0603; Case Metric: 1608; Maximum Working Voltage: 75V; PnP Package: 0603R; Automotive Qualified: False
R611 R621 R628 R632 R634 R642 = gen_R_150R_0603: SMD Resistor 150R 0603; Tolerance: 1%; Power: 0.1W; Case EIA: 0603; Case Metric: 1608; Maximum Working Voltage: 75V; PnP Package: 0603R; Automotive Qualified: True; AEC-Q Grade: Grade 0; AEC-Q Norm: AEC-Q200
R616 R617 R627 R641 = gen_R_5k1_0603: SMD Resistor 5k1 0603; Tolerance: 5%; Power: 0.1W; Case EIA: 0603; Case Metric: 1608; Maximum Working Voltage: 75V; PnP Package: 0603R; Automotive Qualified: True; AEC-Q Norm: AEC-Q200
R618 = gen_R_4R53_0603: SMD Resistor 4R53 0603; Tolerance: 1%; Power: 0.1W; Case EIA: 0603; Case Metric: 1608; Maximum Working Voltage: 75V; PnP Package: 0603R; Automotive Qualified: False
R638 R643 = gen_R_100k_0603: SMD Resistor 100k 0603; Tolerance: 1%; Power: 0.1W; Case EIA: 0603; Case Metric: 1608; Maximum Working Voltage: 75V; PnP Package: 0603R; Automotive Qualified: True; PnP equipped: x
T600 T601 = HM2102NLT: Pulse HM2102NLT BMS Transformer; Automotive Qualified: True; AEC-Q Norm: AEC-Q200
U600 = MC33775A: 14 Cells Battery Cell Controller IC; Manufacturer: NXP; Automotive Qualified: True; AEC-Q Norm: AEC-Q100; AEC-Q Grade: Grade 1
U601 = ACFL-6211T-000E: 15MBd Dual-channel Bi-directional Optocoupler; Manufacturer: Broadcom; PnP Package: 12-BSOP; Automotive Qualified: True; AEC-Q Norm: AEC-Q100; AEC-Q Grade: Grade 1

## Sheet ldo.SchDoc
size A3; DocumentNumber: 8; SheetNumber: 8; SheetTotal: 11; SheetDescription: LDO supply for VDDIO
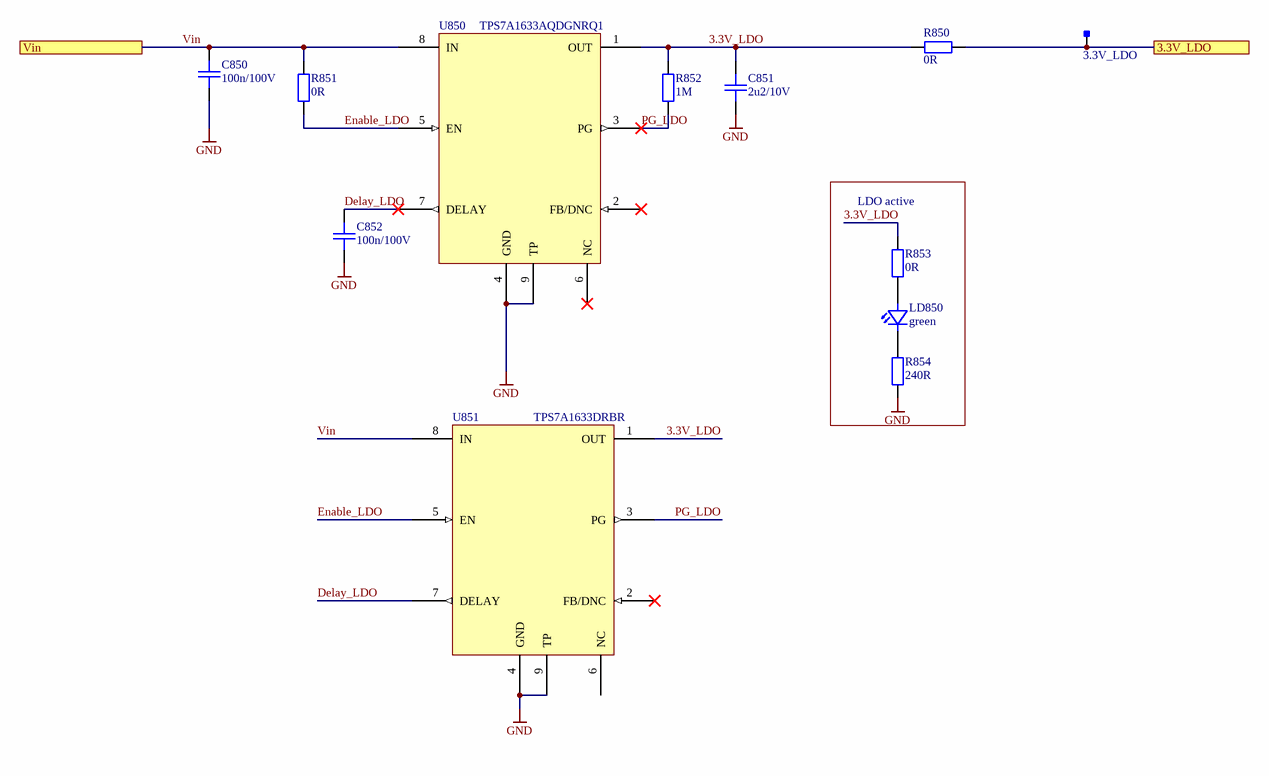
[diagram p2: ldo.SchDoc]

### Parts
3.3V_LDO  Testpoint_Square  [Testpoint_S1]  (value not drawn)  (no BOM)
C850  100n/100V  [CAPC1608X08N]
C851  2u2/10V  [CAPC2012X14N]
C852  100n/100V  [CAPC1608X08N]
LD850  green  [LEDC1608X07N]
R850  0R  [RESC1608X05N]
R851  0R  [RESC1608X05N]
R852  1M  [RESC1608X05N]
R853  0R  [RESC1608X05N]
R854  240R  [RESC1608X05N]
U850  TPS7A1633AQDGNRQ1  [TPS7A16A-Q1]
U851  TPS7A1633DRBR  [TPS7A16_VSON]

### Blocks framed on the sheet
LDO active: LD850 R853 R854

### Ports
3.3V_LDO, Vin

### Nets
GND: C850.1 C851.1 C852.1 R854.1 U850.4(GND) U850.9(TP) U851.4(GND) U851.9(TP)
VDDIO: 3.3V_LDO.1 R850.2 ; port 3.3V_LDO
Vin: C850.2 R851.2 U850.8(IN) U851.8(IN) ; port Vin  [project net VDDC]
3.3V_LDO: C851.2 R850.1 R852.2 R853.2 U850.1(OUT) U851.1(OUT)
Delay_LDO: C852.2 U850.7(DELAY) U851.7(DELAY)
Enable_LDO: R851.1 U850.5(EN) U851.5(EN)
PG_LDO: R852.1 U850.3(PG) U851.3(PG)
NetLD850_1: LD850.1(C) R854.2
NetLD850_2: LD850.2(A) R853.1

Not connected (* = marked no-connect by the designer): U850 2(FB/DNC)* 6(NC)*; U851 2(FB/DNC)* 6(NC)

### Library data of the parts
3.3V_LDO = Testpoint_Square: as ALARM_IN on sheet mc33775
C850 C852 = gen_C_ceramic_100n_100V_X7R_0603: as C601 on sheet mc33775
C851 = gen_C_ceramic_2u2_10V_X7R_0805: MLCC; Capacitance: 2u2; Rated Voltage: 10V; Dielectric: X7R; Case EIA: 0805; Case Metric: 2012; Automotive Qualified: True
LD850 = LED_0603_green_AECQ: as LD600 on sheet mc33775
R850 = gen_R_0R_0603: SMD Resistor 0R 0603; Power: 0.1W; Case EIA: 0603; Case Metric: 1608; Maximum Working Voltage: 75V; PnP Package: 0603R; PnP equipped: x; Automotive Qualified: True
R851 R853 = gen_R_0R_0603: as R100 on sheet slave-14-mc33775
R852 = gen_R_1M_0603: SMD Resistor 1M 0603; Tolerance: 1%; Power: 0.1W; Case EIA: 0603; Case Metric: 1608; Maximum Working Voltage: 75V; PnP Package: 0603R; Automotive Qualified: True
R854 = gen_R_240R_0603: SMD Resistor 240R 0603; Tolerance: 1%; Power: 0.1W; Case EIA: 0603; Case Metric: 1608; Maximum Working Voltage: 75V; PnP Package: 0603R; Automotive Qualified: True; AEC-Q Norm: AEC-Q200
U850 = TPS7A1633AQDGNRQ1: Automotive 60-V, 5-µA IQ, 100-mA low-dropout (LDO) voltage regulator with enable and power good; Manufacturer: Texas Instruments; PnP Package: HVSSOP-8; Automotive Qualified: True; AEC-Q Norm: AEC-Q100; AEC-Q Grade: Grade 1
U851 = TPS7A1633DRBR: Automotive 60-V, 5-µA IQ, 100-mA low-dropout (LDO) voltage regulator with enable and power good; Part Name: TPS7A16A-Q1; Manufacturer: Texas Instruments; PnP Package: VSON-8; Automotive Qualified: False

## Sheet eeprom.SchDoc
size A3; DocumentNumber: 7; SheetNumber: 7; SheetTotal: 11; SheetDescription: EEPROM via I2C
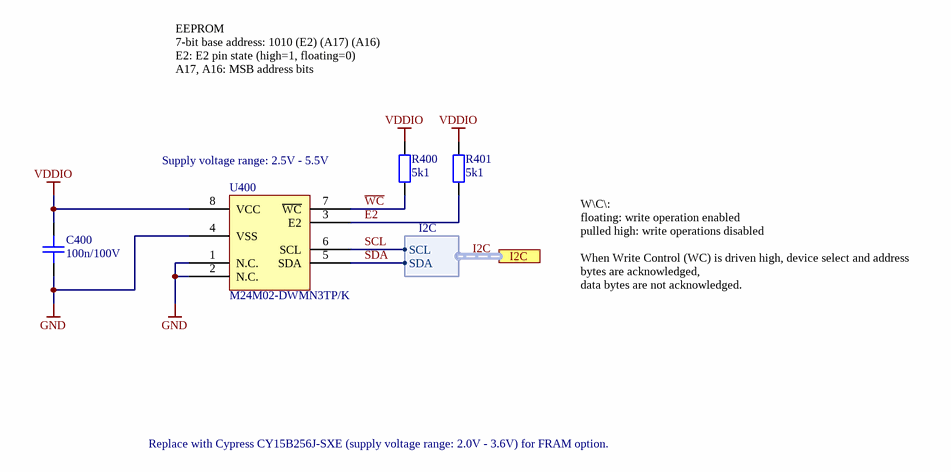
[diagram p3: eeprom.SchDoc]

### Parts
C400  100n/100V  [CAPC1608X08N]
R400  5k1  [RESC1608X05N]
R401  5k1  [RESC1608X05N]
U400  M24M02-DWMN3TP/K  [SOIC127P600X175-8N]

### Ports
I2C (harness I2C)

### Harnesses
I2C: SCL, SDA

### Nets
GND: C400.1 U400.1(N.C.) U400.2(N.C.) U400.4(VSS)
VDDIO: C400.2 R400.2 R401.2 U400.8(VCC)
E2: R401.1 U400.3(E2)
SCL: U400.6(SCL) ; port I2C.SCL  [project net I2C.SCL]
SDA: U400.5(SDA) ; port I2C.SDA  [project net I2C.SDA]
~{WC}: R400.1 U400.7(~{WC})

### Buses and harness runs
harness I2C = port I2C

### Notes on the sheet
- EEPROM
  7-bit base address: 1010 (E2) (A17) (A16)
  E2: E2 pin state (high=1, floating=0)
  A17, A16: MSB address bits
- Supply voltage range: 2.5V - 5.5V
- W\C\:
  floating: write operation enabled
  pulled high: write operations disabled
  When Write Control (WC) is driven high, device select and address bytes are acknowledged,
  data bytes are not acknowledged.
- Replace with Cypress CY15B256J-SXE (supply voltage range: 2.0V - 3.6V) for FRAM option.

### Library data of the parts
C400 = gen_C_ceramic_100n_100V_X7R_0603: as C601 on sheet mc33775
R400 = gen_R_5k1_0603: as R616 on sheet mc33775
R401 = gen_R_5k1_0603: SMD Resistor 5k1 0603; Power: 0.1W; Case EIA: 0603; Case Metric: 1608; Maximum Working Voltage: 75V; PnP Package: 0603R; Automotive Qualified: True; Tolerance: 5%; AEC-Q Norm: AEC-Q200
U400 = M24M02-DWMN3TP/K: Automotive 2-Mbit serial I²C / bus EEPROM with 1 MHz clock; Manufacturer: STMicroelectronics; PnP Package: SO8N; Automotive Qualified: True

## Sheet input_filter.SchDoc
size A3; DocumentNumber: 3; SheetNumber: 3; SheetTotal: 11; SheetDescription: Cell Input Filter
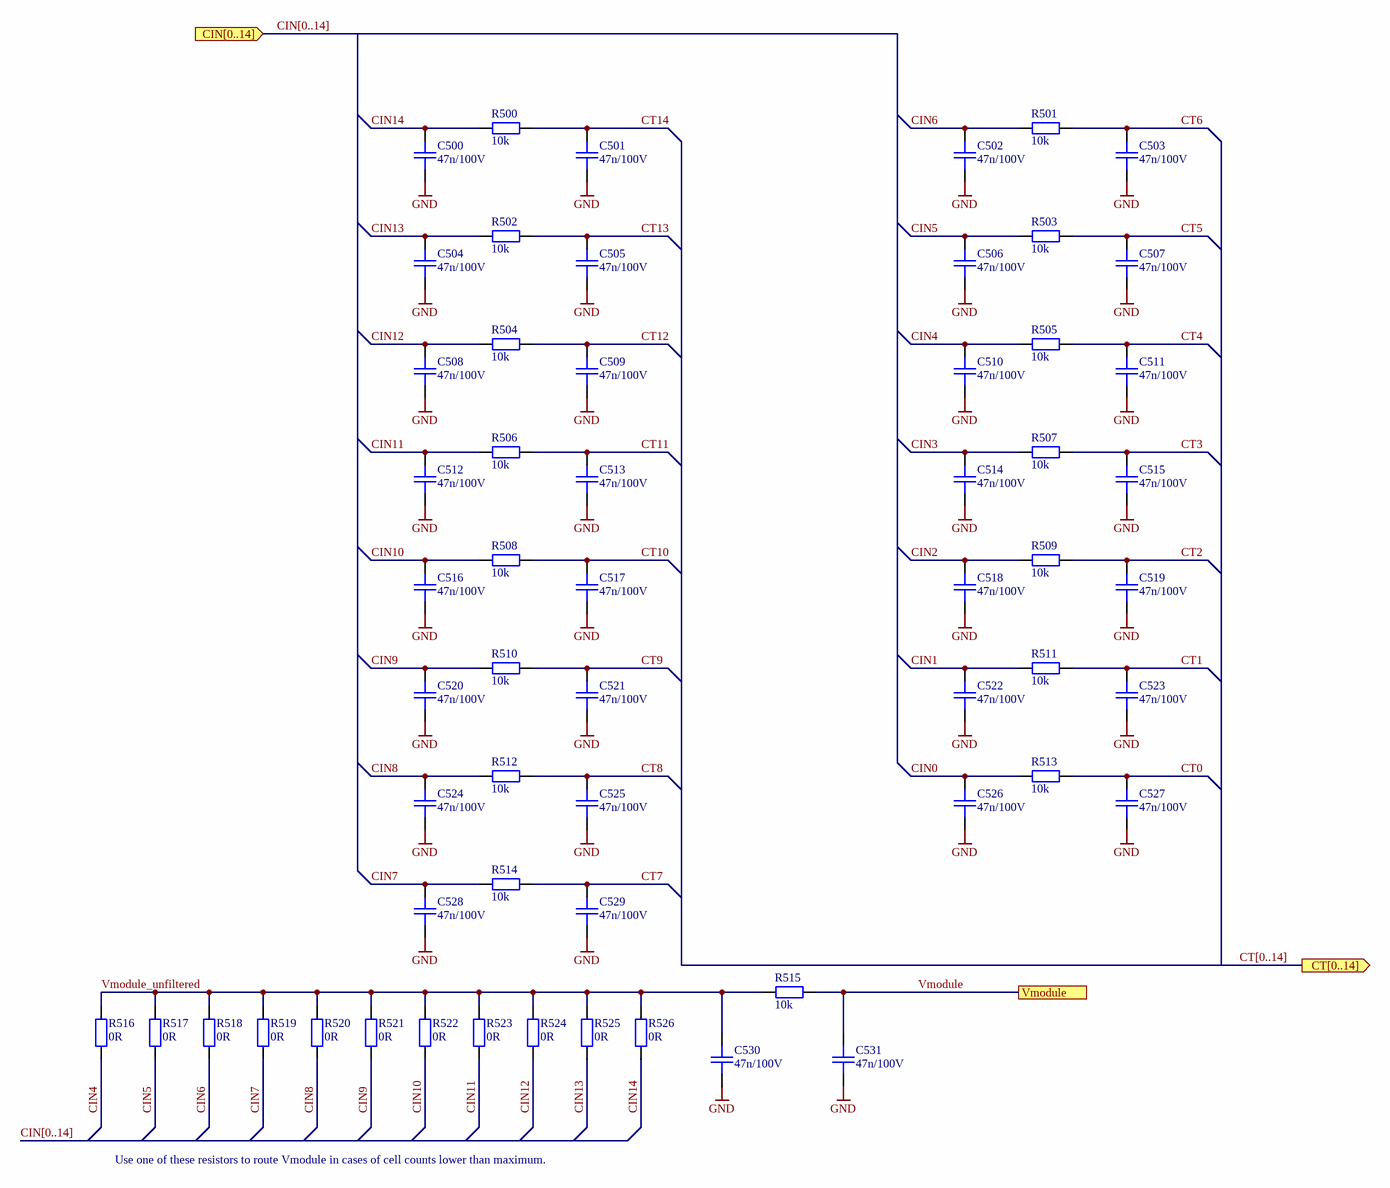
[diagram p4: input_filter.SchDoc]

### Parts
C500  47n/100V  [CAPC1608X08N]
C501  47n/100V  [CAPC1608X08N]
C502  47n/100V  [CAPC1608X08N]
C503  47n/100V  [CAPC1608X08N]
C504  47n/100V  [CAPC1608X08N]
C505  47n/100V  [CAPC1608X08N]
C506  47n/100V  [CAPC1608X08N]
C507  47n/100V  [CAPC1608X08N]
C508  47n/100V  [CAPC1608X08N]
C509  47n/100V  [CAPC1608X08N]
C510  47n/100V  [CAPC1608X08N]
C511  47n/100V  [CAPC1608X08N]
C512  47n/100V  [CAPC1608X08N]
C513  47n/100V  [CAPC1608X08N]
C514  47n/100V  [CAPC1608X08N]
C515  47n/100V  [CAPC1608X08N]
C516  47n/100V  [CAPC1608X08N]
C517  47n/100V  [CAPC1608X08N]
C518  47n/100V  [CAPC1608X08N]
C519  47n/100V  [CAPC1608X08N]
C520  47n/100V  [CAPC1608X08N]
C521  47n/100V  [CAPC1608X08N]
C522  47n/100V  [CAPC1608X08N]
C523  47n/100V  [CAPC1608X08N]
C524  47n/100V  [CAPC1608X08N]
C525  47n/100V  [CAPC1608X08N]
C526  47n/100V  [CAPC1608X08N]
C527  47n/100V  [CAPC1608X08N]
C528  47n/100V  [CAPC1608X08N]
C529  47n/100V  [CAPC1608X08N]
C530  47n/100V  [CAPC1608X08N]
C531  47n/100V  [CAPC1608X08N]
R500  10k  [RESC1608X05N]
R501  10k  [RESC1608X05N]
R502  10k  [RESC1608X05N]
R503  10k  [RESC1608X05N]
R504  10k  [RESC1608X05N]
R505  10k  [RESC1608X05N]
R506  10k  [RESC1608X05N]
R507  10k  [RESC1608X05N]
R508  10k  [RESC1608X05N]
R509  10k  [RESC1608X05N]
R510  10k  [RESC1608X05N]
R511  10k  [RESC1608X05N]
R512  10k  [RESC1608X05N]
R513  10k  [RESC1608X05N]
R514  10k  [RESC1608X05N]
R515  10k  [RESC1608X05N]
R516  0R  [RESC1608X05N]
R517  0R  [RESC1608X05N]
R518  0R  [RESC1608X05N]
R519  0R  [RESC1608X05N]
R520  0R  [RESC1608X05N]
R521  0R  [RESC1608X05N]
R522  0R  [RESC1608X05N]
R523  0R  [RESC1608X05N]
R524  0R  [RESC1608X05N]
R525  0R  [RESC1608X05N]
R526  0R  [RESC1608X05N]

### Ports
CIN[0..14] (in), CT[0..14] (out), Vmodule

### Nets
GND: C500.1 C501.1 C502.1 C503.1 C504.1 C505.1 C506.1 C507.1 C508.1 C509.1 C510.1 C511.1 C512.1 C513.1 C514.1 C515.1 C516.1 C517.1 C518.1 C519.1 C520.1 C521.1 C522.1 C523.1 C524.1 C525.1 C526.1 C527.1 C528.1 C529.1 C530.1 C531.1
VMODULE: C531.2 R515.1 ; port Vmodule
CIN0: C526.2 R513.2
CIN1: C522.2 R511.2  [project net BAL.CB_COM1]
CIN2: C518.2 R509.2
CIN3: C514.2 R507.2  [project net BAL.CB_COM3]
CIN4: C510.2 R505.2 R516.1
CIN5: C506.2 R503.2 R517.1  [project net BAL.CB_COM5]
CIN6: C502.2 R501.2 R518.1
CIN7: C528.2 R514.2 R519.1  [project net BAL.CB_COM7]
CIN8: C524.2 R512.2 R520.1
CIN9: C520.2 R510.2 R521.1  [project net BAL.CB_COM9]
CIN10: C516.2 R508.2 R522.1
CIN11: C512.2 R506.2 R523.1  [project net BAL.CB_COM11]
CIN12: C508.2 R504.2 R524.1
CIN13: C504.2 R502.2 R525.1  [project net BAL.CB_COM13]
CIN14: C500.2 R500.2 R526.1
CT0: C527.2 R513.1
CT1: C523.2 R511.1
CT2: C519.2 R509.1
CT3: C515.2 R507.1
CT4: C511.2 R505.1
CT5: C507.2 R503.1
CT6: C503.2 R501.1
CT7: C529.2 R514.1
CT8: C525.2 R512.1
CT9: C521.2 R510.1
CT10: C517.2 R508.1
CT11: C513.2 R506.1
CT12: C509.2 R504.1
CT13: C505.2 R502.1
CT14: C501.2 R500.1
Vmodule_unfiltered: C530.2 R515.2 R516.2 R517.2 R518.2 R519.2 R520.2 R521.2 R522.2 R523.2 R524.2 R525.2 R526.2

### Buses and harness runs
bus CIN[0..14]
bus CIN[0..14] = port CIN[0..14]
bus CT[0..14] = port CT[0..14]

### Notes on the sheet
- Use one of these resistors to route Vmodule in cases of cell counts lower than maximum.

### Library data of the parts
C500-C531 = gen_C_ceramic_47n_100V_X7R_0603: as C600 on sheet mc33775
R500-R515 = gen_R_10k_0603: SMD Resistor 10k 0603; Tolerance: 1%; Power: 0.1W; Case EIA: 0603; Case Metric: 1608; Maximum Working Voltage: 75V; PnP Package: 0603R; Automotive Qualified: True
R516-R526 = gen_R_0R_0603: as R100 on sheet slave-14-mc33775

## Sheet passive_balancing.SchDoc
size A3; DocumentNumber: 4; SheetNumber: 4; SheetTotal: 11; SheetDescription: Passive Balancing
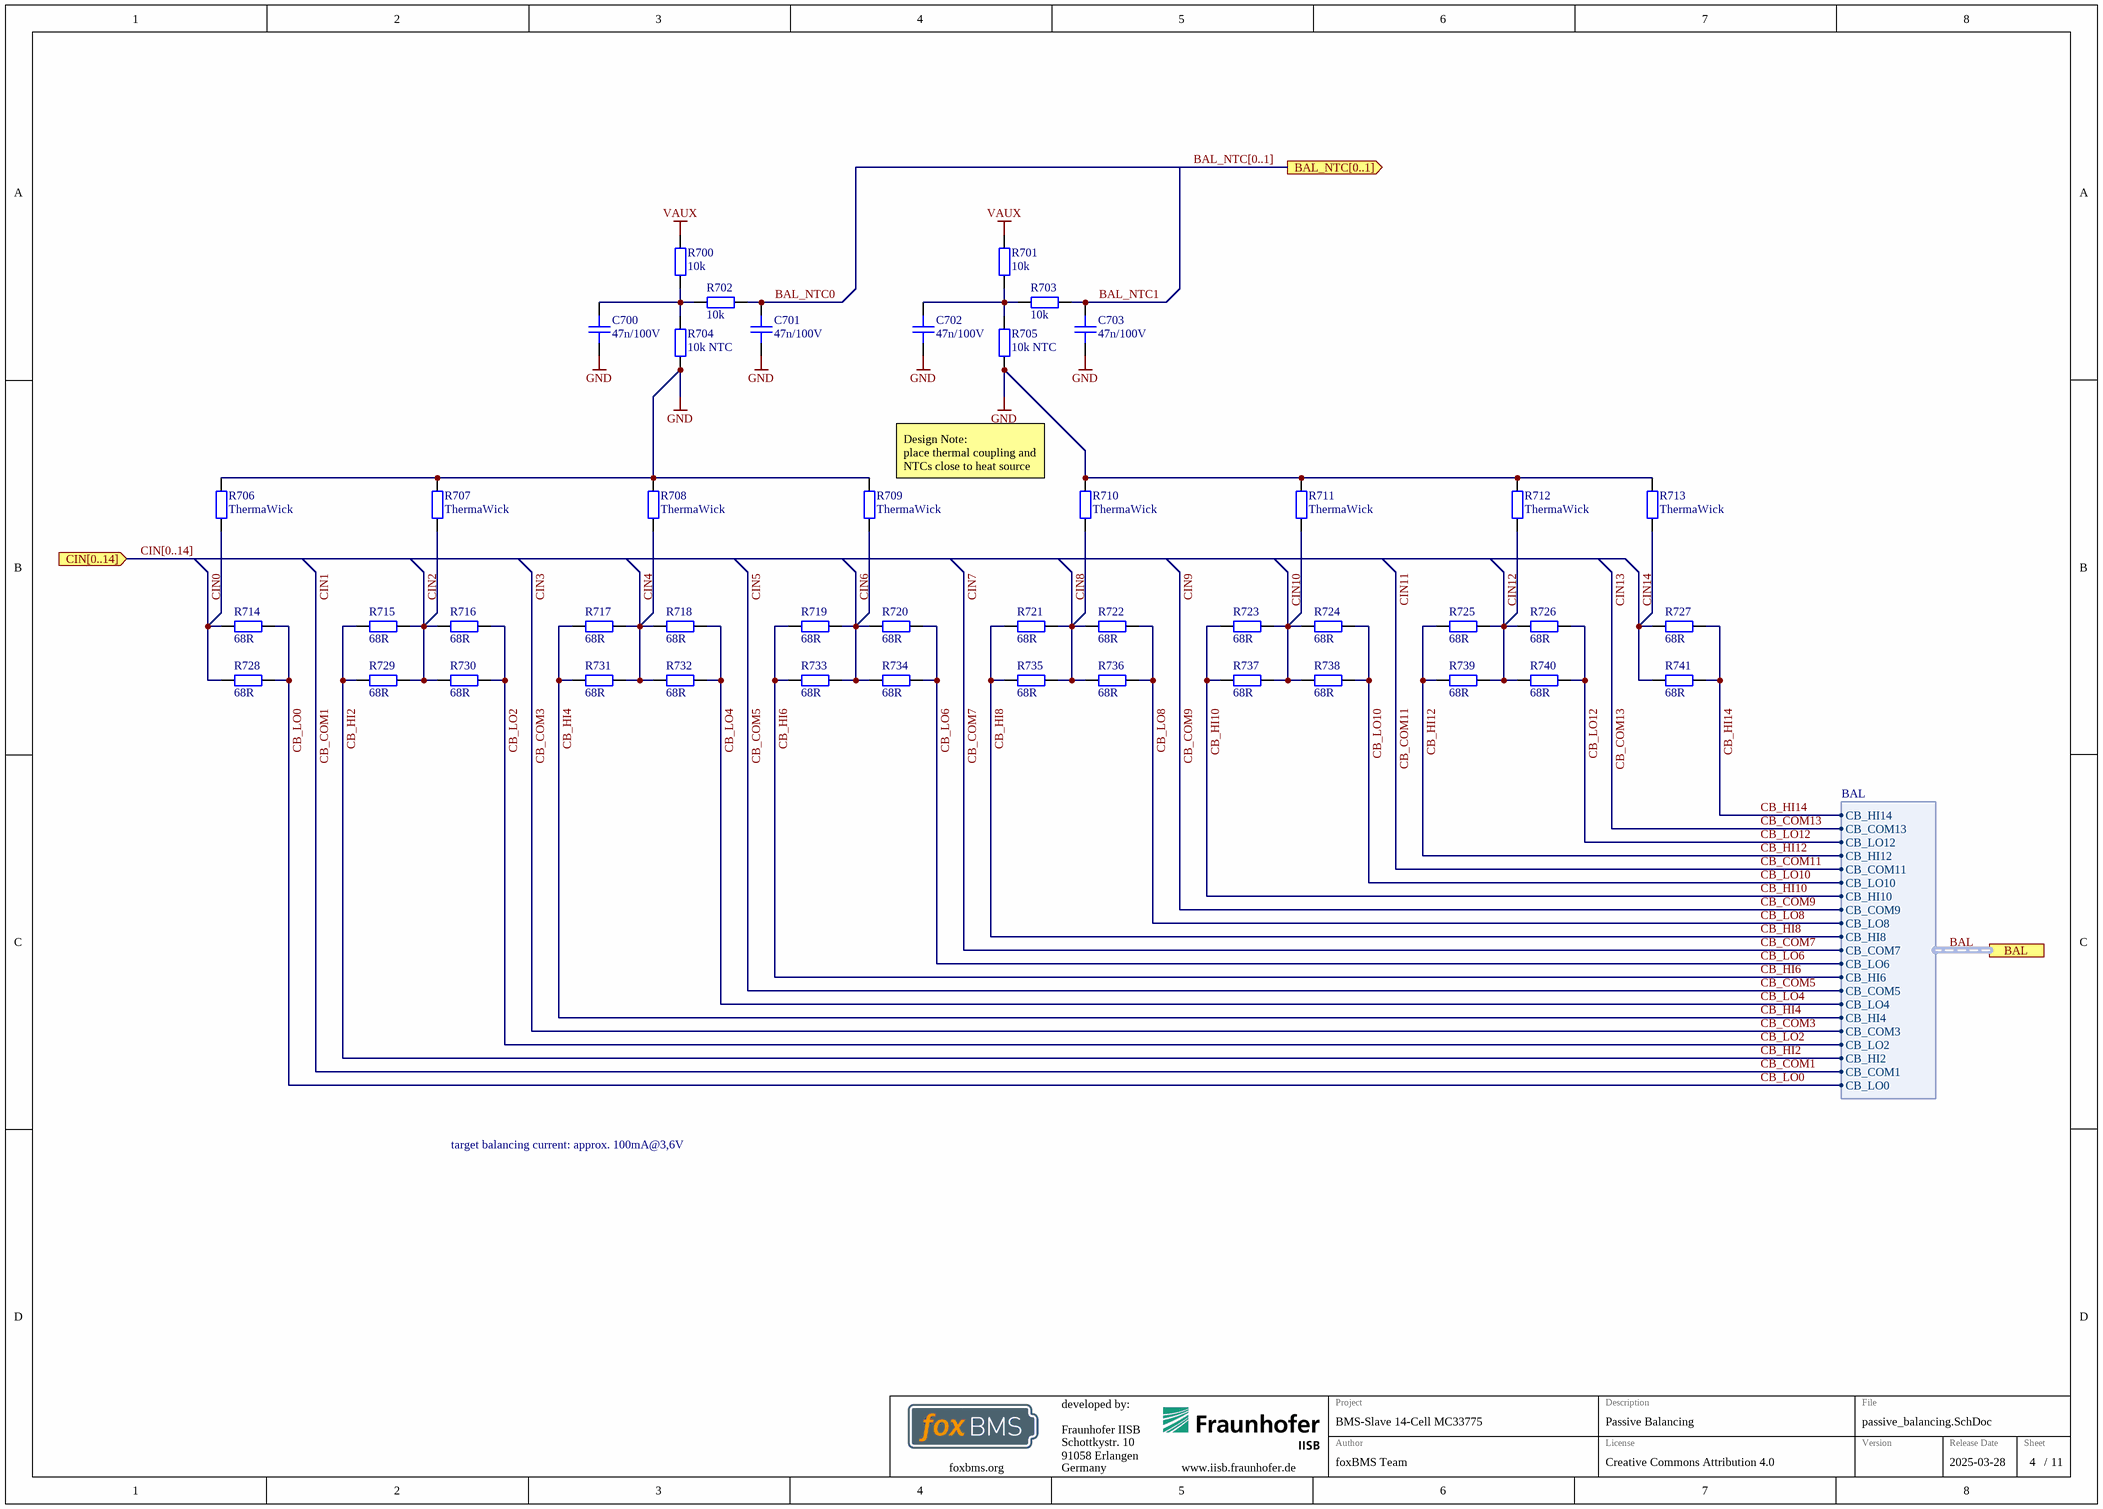
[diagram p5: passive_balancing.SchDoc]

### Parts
C700  47n/100V  [CAPC1608X08N]
C701  47n/100V  [CAPC1608X08N]
C702  47n/100V  [CAPC1608X08N]
C703  47n/100V  [CAPC1608X08N]
R700  10k  [RESC1608X05N]
R701  10k  [RESC1608X05N]
R702  10k  [RESC1608X05N]
R703  10k  [RESC1608X05N]
R704  10k NTC  [RESC1005X04N]
R705  10k NTC  [RESC1005X04N]
R706  ThermaWick  [Vishay_THJP_0603]
R707  ThermaWick  [Vishay_THJP_0603]
R708  ThermaWick  [Vishay_THJP_0603]
R709  ThermaWick  [Vishay_THJP_0603]
R710  ThermaWick  [Vishay_THJP_0603]
R711  ThermaWick  [Vishay_THJP_0603]
R712  ThermaWick  [Vishay_THJP_0603]
R713  ThermaWick  [Vishay_THJP_0603]
R714  68R  [RESC5025X07N]
R715  68R  [RESC5025X07N]
R716  68R  [RESC5025X07N]
R717  68R  [RESC5025X07N]
R718  68R  [RESC5025X07N]
R719  68R  [RESC5025X07N]
R720  68R  [RESC5025X07N]
R721  68R  [RESC5025X07N]
R722  68R  [RESC5025X07N]
R723  68R  [RESC5025X07N]
R724  68R  [RESC5025X07N]
R725  68R  [RESC5025X07N]
R726  68R  [RESC5025X07N]
R727  68R  [RESC5025X07N]
R728  68R  [RESC5025X07N]
R729  68R  [RESC5025X07N]
R730  68R  [RESC5025X07N]
R731  68R  [RESC5025X07N]
R732  68R  [RESC5025X07N]
R733  68R  [RESC5025X07N]
R734  68R  [RESC5025X07N]
R735  68R  [RESC5025X07N]
R736  68R  [RESC5025X07N]
R737  68R  [RESC5025X07N]
R738  68R  [RESC5025X07N]
R739  68R  [RESC5025X07N]
R740  68R  [RESC5025X07N]
R741  68R  [RESC5025X07N]

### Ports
BAL (harness BAL), BAL_NTC[0..1] (out), CIN[0..14] (in)

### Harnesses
BAL: CB_HI14, CB_COM13, CB_LO12, CB_HI12, CB_COM11, CB_LO10, CB_HI10, CB_COM9, CB_LO8, CB_HI8, CB_COM7, CB_LO6, CB_HI6, CB_COM5, CB_LO4, CB_HI4, CB_COM3, CB_LO2, CB_HI2, CB_COM1, CB_LO0

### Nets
GND: C700.1 C701.1 C702.1 C703.1 R704.2 R705.2 R706.2 R707.2 R708.2 R709.2 R710.2 R711.2 R712.2 R713.2
VAUX: R700.2 R701.2
BAL_NTC0: C701.2 R702.1
BAL_NTC1: C703.2 R703.1
CB_HI2: R715.2 R729.2 ; port BAL.CB_HI2  [project net BAL.CB_HI2]
CB_HI4: R717.2 R731.2 ; port BAL.CB_HI4  [project net BAL.CB_HI4]
CB_HI6: R719.2 R733.2 ; port BAL.CB_HI6  [project net BAL.CB_HI6]
CB_HI8: R721.2 R735.2 ; port BAL.CB_HI8  [project net BAL.CB_HI8]
CB_HI10: R723.2 R737.2 ; port BAL.CB_HI10  [project net BAL.CB_HI10]
CB_HI12: R725.2 R739.2 ; port BAL.CB_HI12  [project net BAL.CB_HI12]
CB_HI14: R727.1 R741.1 ; port BAL.CB_HI14  [project net BAL.CB_HI14]
CB_LO0: R714.1 R728.1 ; port BAL.CB_LO0  [project net BAL.CB_LO0]
CB_LO2: R716.1 R730.1 ; port BAL.CB_LO2  [project net BAL.CB_LO2]
CB_LO4: R718.1 R732.1 ; port BAL.CB_LO4  [project net BAL.CB_LO4]
CB_LO6: R720.1 R734.1 ; port BAL.CB_LO6  [project net BAL.CB_LO6]
CB_LO8: R722.1 R736.1 ; port BAL.CB_LO8  [project net BAL.CB_LO8]
CB_LO10: R724.1 R738.1 ; port BAL.CB_LO10  [project net BAL.CB_LO10]
CB_LO12: R726.1 R740.1 ; port BAL.CB_LO12  [project net BAL.CB_LO12]
CIN0: R706.1 R714.2 R728.2
CIN2: R707.1 R715.1 R716.2 R729.1 R730.2
CIN4: R708.1 R717.1 R718.2 R731.1 R732.2
CIN6: R709.1 R719.1 R720.2 R733.1 R734.2
CIN8: R710.1 R721.1 R722.2 R735.1 R736.2
CIN10: R711.1 R723.1 R724.2 R737.1 R738.2
CIN12: R712.1 R725.1 R726.2 R739.1 R740.2
CIN14: R713.1 R727.2 R741.2
NetC700_2: C700.2 R700.1 R702.2 R704.1
NetC702_2: C702.2 R701.1 R703.2 R705.1

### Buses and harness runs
bus BAL_NTC[0..1] = port BAL_NTC[0..1]
bus CIN[0..14] = port CIN[0..14]
harness BAL = port BAL

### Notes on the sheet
- Design Note:
  place thermal coupling and NTCs close to heat source
- target balancing current: approx. 100mA@3,6V

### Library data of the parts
C700-C703 = gen_C_ceramic_47n_100V_X7R_0603: as C600 on sheet mc33775
R700-R703 = gen_R_10k_0603: as R500 on sheet input_filter
R704 R705 = gen_R_10k_NTC_0402: SMD Resistor 10k NTC 0402; Power: 0.150W; Case EIA: 0402; Maximum Working Voltage: 50V; Automotive Qualified: True
R706-R713 = Vishay_THJP_0603: ThermaWick thermal coupling 0603; Case EIA: 0603; Maximum Working Voltage: 1.5kV; Automotive Qualified: False
R714-R741 = gen_R_68R_2010: SMD Resistor 68R 2010; Tolerance: 1%; Power: 0.75W; Case EIA: 2010; Case Metric: 5025; Maximum Working Voltage: 200V; PnP Package: 2010R; Automotive Qualified: True

## Sheet analog_in.SchDoc
size A3; DocumentNumber: 5; SheetNumber: 5; SheetTotal: 11; AUTHOR: Fraunhofer IISB foxBMS Team; SheetDescription: I2C analog multiplexer for temperature inputs
Used 2 times, as channels U_analog_in_bank0, U_analog_in_bank1. Parts and nets are listed once, with the designators drawn on the sheet.
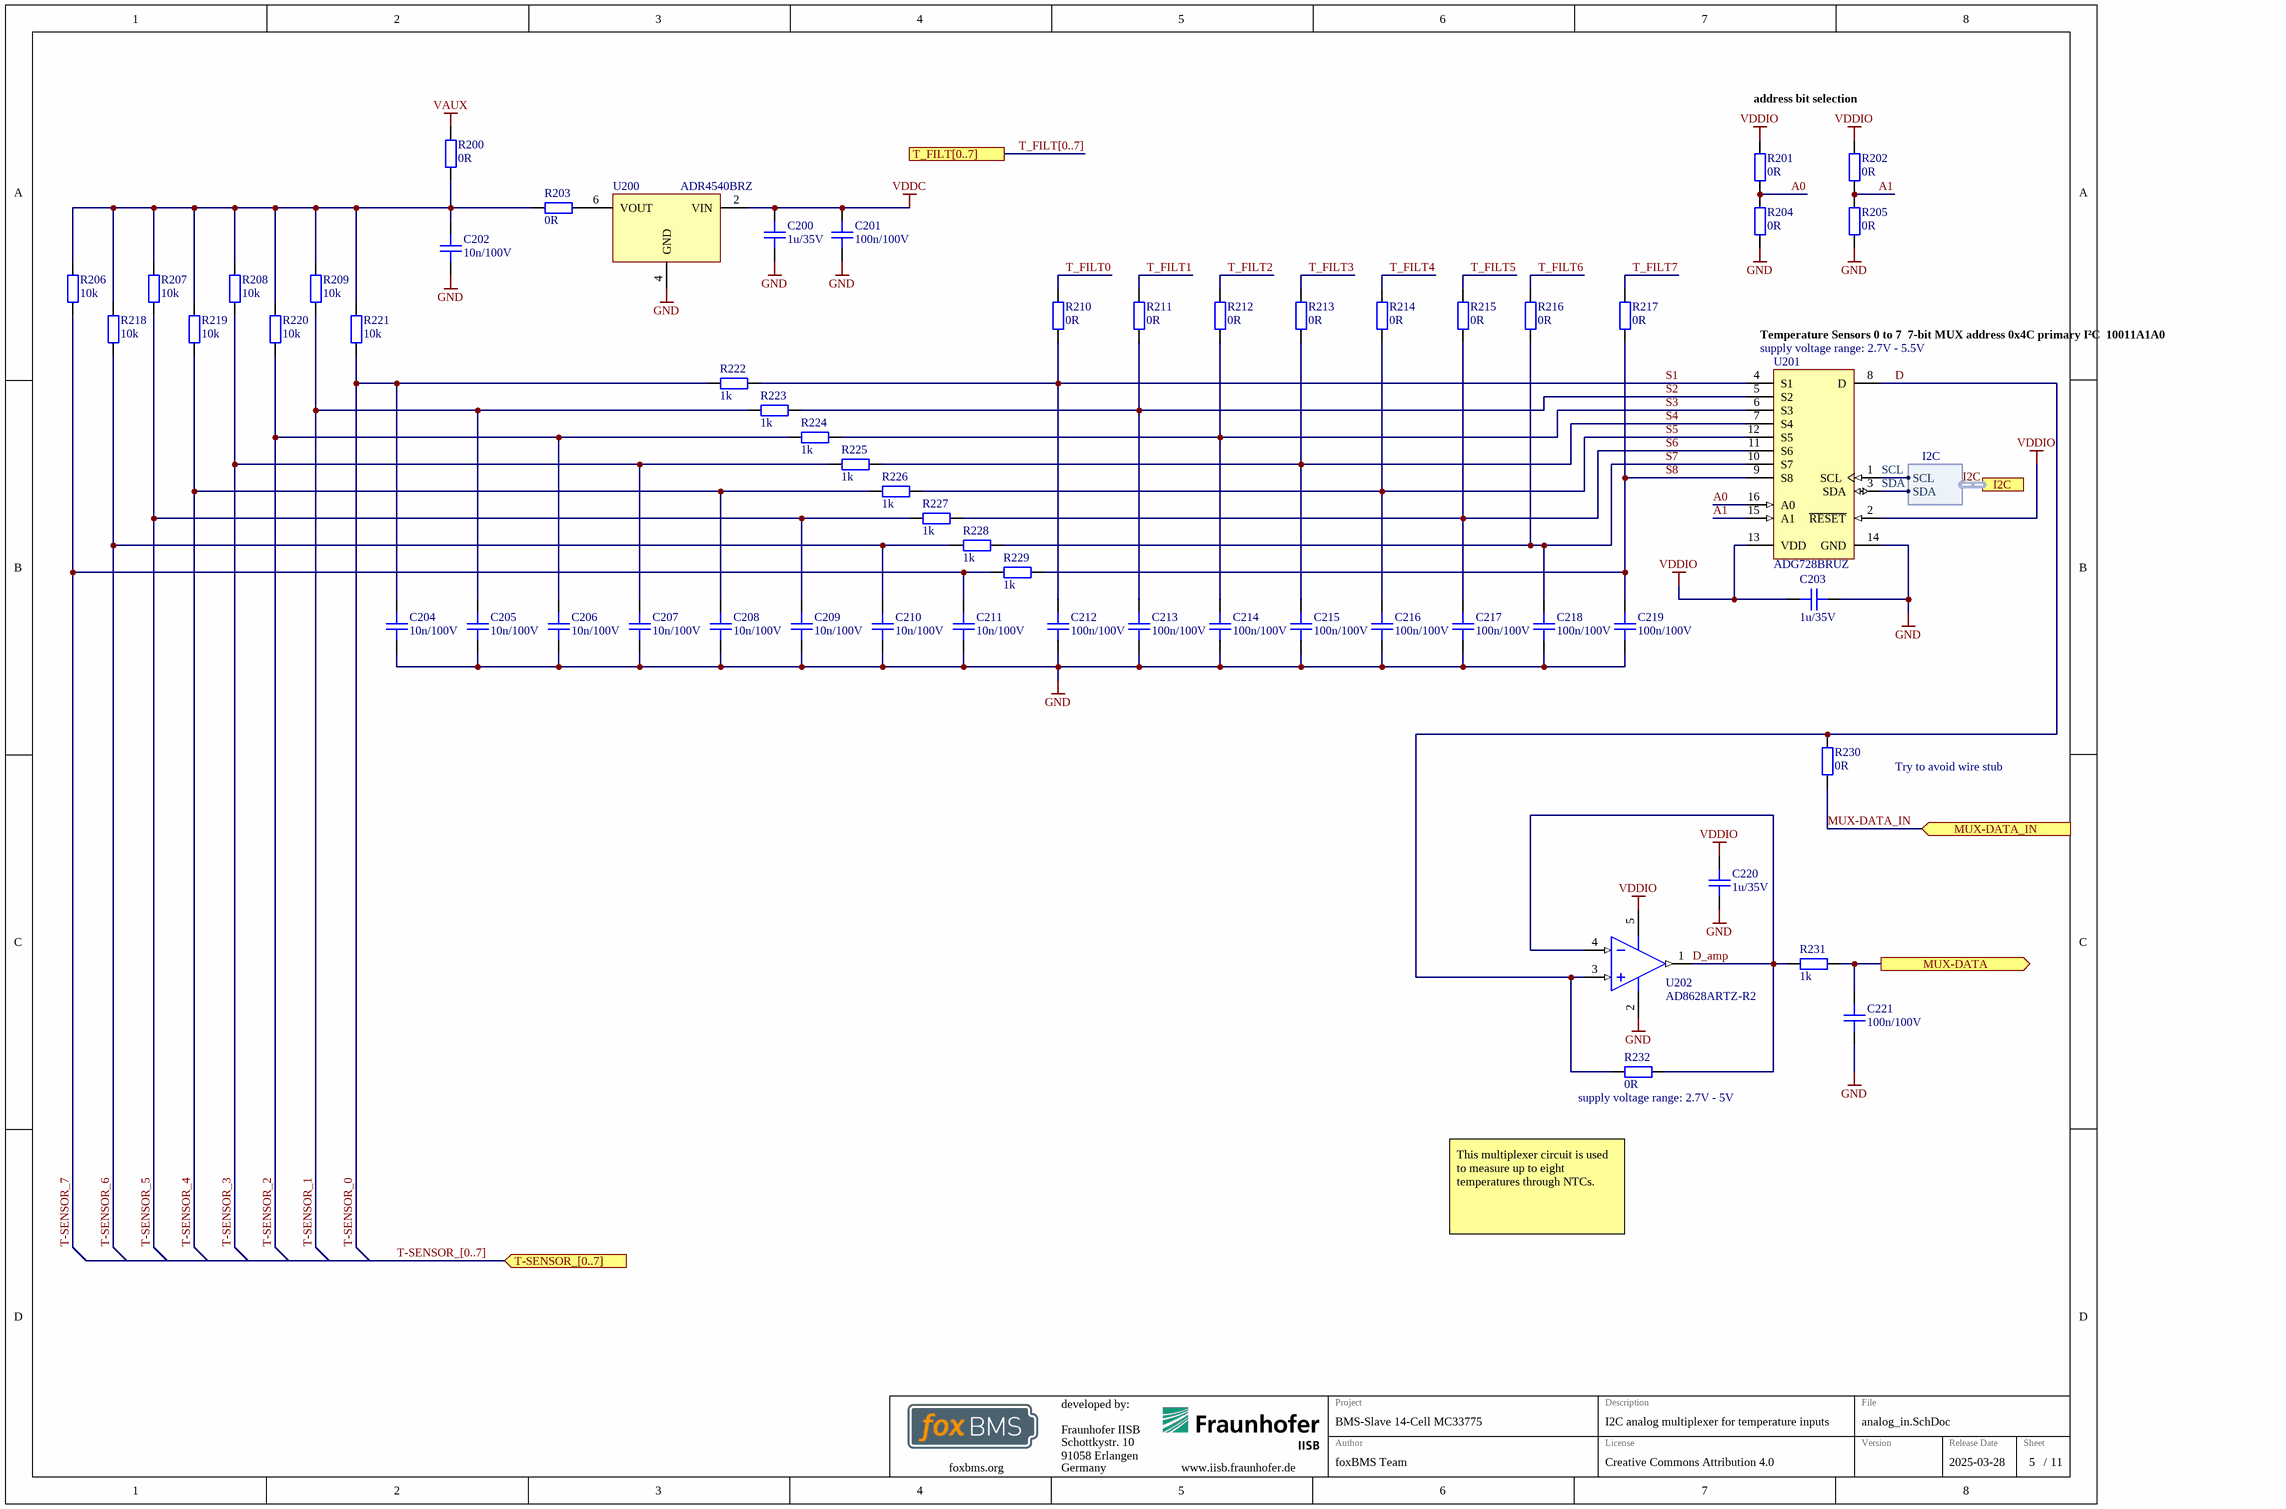
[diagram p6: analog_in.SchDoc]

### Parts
C200  1u/35V  [CAPC1608X08N]
C201  100n/100V  [CAPC1608X08N]
C202  10n/100V  [CAPC1608X08N]
C203  1u/35V  [CAPC1608X08N]
C204  10n/100V  [CAPC1608X08N]
C205  10n/100V  [CAPC1608X08N]
C206  10n/100V  [CAPC1608X08N]
C207  10n/100V  [CAPC1608X08N]
C208  10n/100V  [CAPC1608X08N]
C209  10n/100V  [CAPC1608X08N]
C210  10n/100V  [CAPC1608X08N]
C211  10n/100V  [CAPC1608X08N]
C212  100n/100V  [CAPC1608X08N]
C213  100n/100V  [CAPC1608X08N]
C214  100n/100V  [CAPC1608X08N]
C215  100n/100V  [CAPC1608X08N]
C216  100n/100V  [CAPC1608X08N]
C217  100n/100V  [CAPC1608X08N]
C218  100n/100V  [CAPC1608X08N]
C219  100n/100V  [CAPC1608X08N]
C220  1u/35V  [CAPC1608X08N]
C221  100n/100V  [CAPC1608X08N]
R200  0R  [RESC1608X05N]
R201  0R  [RESC1608X05N]
R202  0R  [RESC1608X05N]
R203  0R  [RESC1608X05N]
R204  0R  [RESC1608X05N]
R205  0R  [RESC1608X05N]
R206  10k  [RESC1608X05N]
R207  10k  [RESC1608X05N]
R208  10k  [RESC1608X05N]
R209  10k  [RESC1608X05N]
R210  0R  [RESC1608X05N]
R211  0R  [RESC1608X05N]
R212  0R  [RESC1608X05N]
R213  0R  [RESC1608X05N]
R214  0R  [RESC1608X05N]
R215  0R  [RESC1608X05N]
R216  0R  [RESC1608X05N]
R217  0R  [RESC1608X05N]
R218  10k  [RESC1608X05N]
R219  10k  [RESC1608X05N]
R220  10k  [RESC1608X05N]
R221  10k  [RESC1608X05N]
R222  1k  [RESC1608X05N]
R223  1k  [RESC1608X05N]
R224  1k  [RESC1608X05N]
R225  1k  [RESC1608X05N]
R226  1k  [RESC1608X05N]
R227  1k  [RESC1608X05N]
R228  1k  [RESC1608X05N]
R229  1k  [RESC1608X05N]
R230  0R  [RESC1608X05N]
R231  1k  [RESC1608X05N]
R232  0R  [RESC1608X05N]
U200  ADR4540BRZ  [SOIC127P600X175-8N]
U201  ADG728BRUZ  [ADI-RU-16_M]
U202  AD8628ARTZ-R2  [ADI-RJ-5_M]

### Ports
I2C (harness I2C), MUX-DATA (out), MUX-DATA_IN (in), T-SENSOR_[0..7] (in), T_FILT[0..7]

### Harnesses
I2C: SCL, SDA

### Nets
GND: C200.1 C201.1 C202.1 C203.1 C204.1 C205.1 C206.1 C207.1 C208.1 C209.1 C210.1 C211.1 C212.1 C213.1 C214.1 C215.1 C216.1 C217.1 C218.1 C219.1 C220.1 C221.1 R204.1 R205.1 U200.4(GND) U201.14(GND) U202.2(-V)
VAUX: R200.2
VDDC: C200.2 C201.2 U200.2(VIN)
VDDIO: C203.2 C220.2 R201.2 R202.2 U201.2(~{RESET}) U201.13(VDD) U202.5(+V)
A0: R201.1 R204.2 U201.16(A0)
A1: R202.1 R205.2 U201.15(A1)
D: R230.1 R232.1 U201.8(D) U202.3(+IN)
D_amp: R231.1 R232.2 U202.1(OUT) U202.4(-IN)
MUX-DATA: C221.2 R231.2 ; port MUX-DATA
MUX-DATA_IN: R230.2 ; port MUX-DATA_IN
S1: C212.2 R210.1 R222.1 U201.4(S1)
S2: C213.2 R211.1 R223.1 U201.5(S2)
S3: C214.2 R212.1 R224.1 U201.6(S3)
S4: C215.2 R213.1 R225.1 U201.7(S4)
S5: C216.2 R214.1 R226.1 U201.12(S5)
S6: C217.2 R215.1 R227.1 U201.11(S6)
S7: C218.2 R216.1 R228.1 U201.10(S7)
S8: C219.2 R217.1 R229.1 U201.9(S8)
SCL: U201.1(SCL) ; port I2C.SCL  [project net I2C.SCL]
SDA: U201.3(SDA) ; port I2C.SDA  [project net I2C.SDA]
T-SENSOR_0: C204.2 R221.1 R222.2
T-SENSOR_1: C205.2 R209.1 R223.2
T-SENSOR_2: C206.2 R220.1 R224.2
T-SENSOR_3: C207.2 R208.1 R225.2
T-SENSOR_4: C208.2 R219.1 R226.2
T-SENSOR_5: C209.2 R207.1 R227.2
T-SENSOR_6: C210.2 R218.1 R228.2
T-SENSOR_7: C211.2 R206.1 R229.2
T_FILT0: R210.2
T_FILT1: R211.2
T_FILT2: R212.2
T_FILT3: R213.2
T_FILT4: R214.2
T_FILT5: R215.2
T_FILT6: R216.2
T_FILT7: R217.2
NetC202_2: C202.2 R200.1 R203.1 R206.2 R207.2 R208.2 R209.2 R218.2 R219.2 R220.2 R221.2
NetR203_2: R203.2 U200.6(VOUT)

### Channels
U_analog_in_bank0: designators end in _1; ports MUX-DATA=MUX_DATA MUX-DATA_IN=MUX-DATA_IN
U_analog_in_bank1: designators end in _2; ports MUX-DATA=MUX_DATA2 MUX-DATA_IN=MUX-DATA_IN_U_analog_in_bank1

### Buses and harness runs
bus T-SENSOR_[0..7] = port T-SENSOR_[0..7]
bus T_FILT[0..7] = port T_FILT[0..7]
harness I2C = port I2C

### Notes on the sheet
- address bit selection
- (near U201) Temperature Sensors 0 to 7
  7-bit MUX address 0x4C primary I²C
  10011A1A0
- (near U201) supply voltage range: 2.7V - 5.5V
- Try to avoid wire stub
- (near R232) supply voltage range: 2.7V - 5V
- This multiplexer circuit is used to measure up to eight temperatures through NTCs.

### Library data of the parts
C200 = gen_C_ceramic_1u_35V_X7R_0603: MLCC; Capacitance: 1u; Rated Voltage: 35V; Dielectric: X7R; Case EIA: 0603; Case Metric: 1608; PnP Package: 0603C; PnP Value: 1uF/35V/X7R; PnP equipped: x; Automotive Qualified: True; AEC-Q Norm: AEC-Q200
C201 C212-C219 C221 = gen_C_ceramic_100n_100V_X7R_0603: as C601 on sheet mc33775
C202 = gen_C_ceramic_10n_100V_X7R_0603: MLCC; Capacitance: 10n; Rated Voltage: 100V; Dielectric: X7R; Case EIA: 0603; Case Metric: 1608; Automotive Qualified: True; PnP Package: 0603C; PnP Value: 10nF/100V/X7R; AEC-Q Norm: AEC-Q200
C203 C220 = gen_C_ceramic_1u_35V_X7R_0603: MLCC; Capacitance: 1u; Rated Voltage: 35V; Dielectric: X7R; Case EIA: 0603; Case Metric: 1608; Automotive Qualified: True; PnP Package: 0603C; PnP Value: 1uF/35V/X7R; PnP equipped: x; AEC-Q Norm: AEC-Q200
C204-C211 = gen_C_ceramic_10n_100V_X7R_0603: as C607 on sheet mc33775
R200-R205 R210-R217 R230 R232 = gen_R_0R_0603: as R100 on sheet slave-14-mc33775
R206-R209 R218-R221 = gen_R_10k_0603: as R500 on sheet input_filter
R222-R229 R231 = gen_R_1k_0603: SMD Resistor 1k 0603; Tolerance: 1%; Power: 0.1W; Case EIA: 0603; Case Metric: 1608; Maximum Working Voltage: 75V; PnP Package: 0603R; Automotive Qualified: True; PnP equipped: x
U200 = ADR4540BRZ: Ultralow Noise, High Accuracy 4.096V Reference; Manufacturer: Analog Devices; PnP Package: SO-8; Automotive Qualified: True; AEC-Q Norm: AEC-Q100; AEC-Q Grade: unknown
U201 = CMP-0798-00197-1: CMOS, Low Voltage, 2-Wire Serially Controlled, Matrix Switch, -40 to 85 degC, 16-pin SOP (RU-16), Tube; Manufacturer: Analog Devices; Ron (ohms): 2.5; Supply V Guar Performance: Single_(+3V), Single_(+5V); Max Analog Signal Range: 0 to Vdd; Bandwidth (Hz): 65M
U202 = CMP-0384-01512-2: Single Channel RRIO Operational Amplifier, 2.5 MHz BW, 1 V/us SR, Industrial, 5-pin SOT23 (RJ-5), Reel; Manufacturer: Analog Devices; Generic Part Number: AD8628; Iq/Amp: 1.1mA; Automotive Qualified: Yes; V Span Max: 6V; Input Bias Current: 30pA; Slew Rate: 1V/us; Amplifiers Per Package: 1; Input Offset Voltage: 1uV; Small Signal Bandwidth: 2.5MHz; V Span Min: 2.7V

## Sheet connectors.SchDoc: foxBMS BMS-Slave 12-Cell
size A3; DocumentNumber: 6; SheetNumber: 6; SheetTotal: 11; AUTHOR: Fraunhofer IISB foxBMS Team; SheetDescription: Connectors
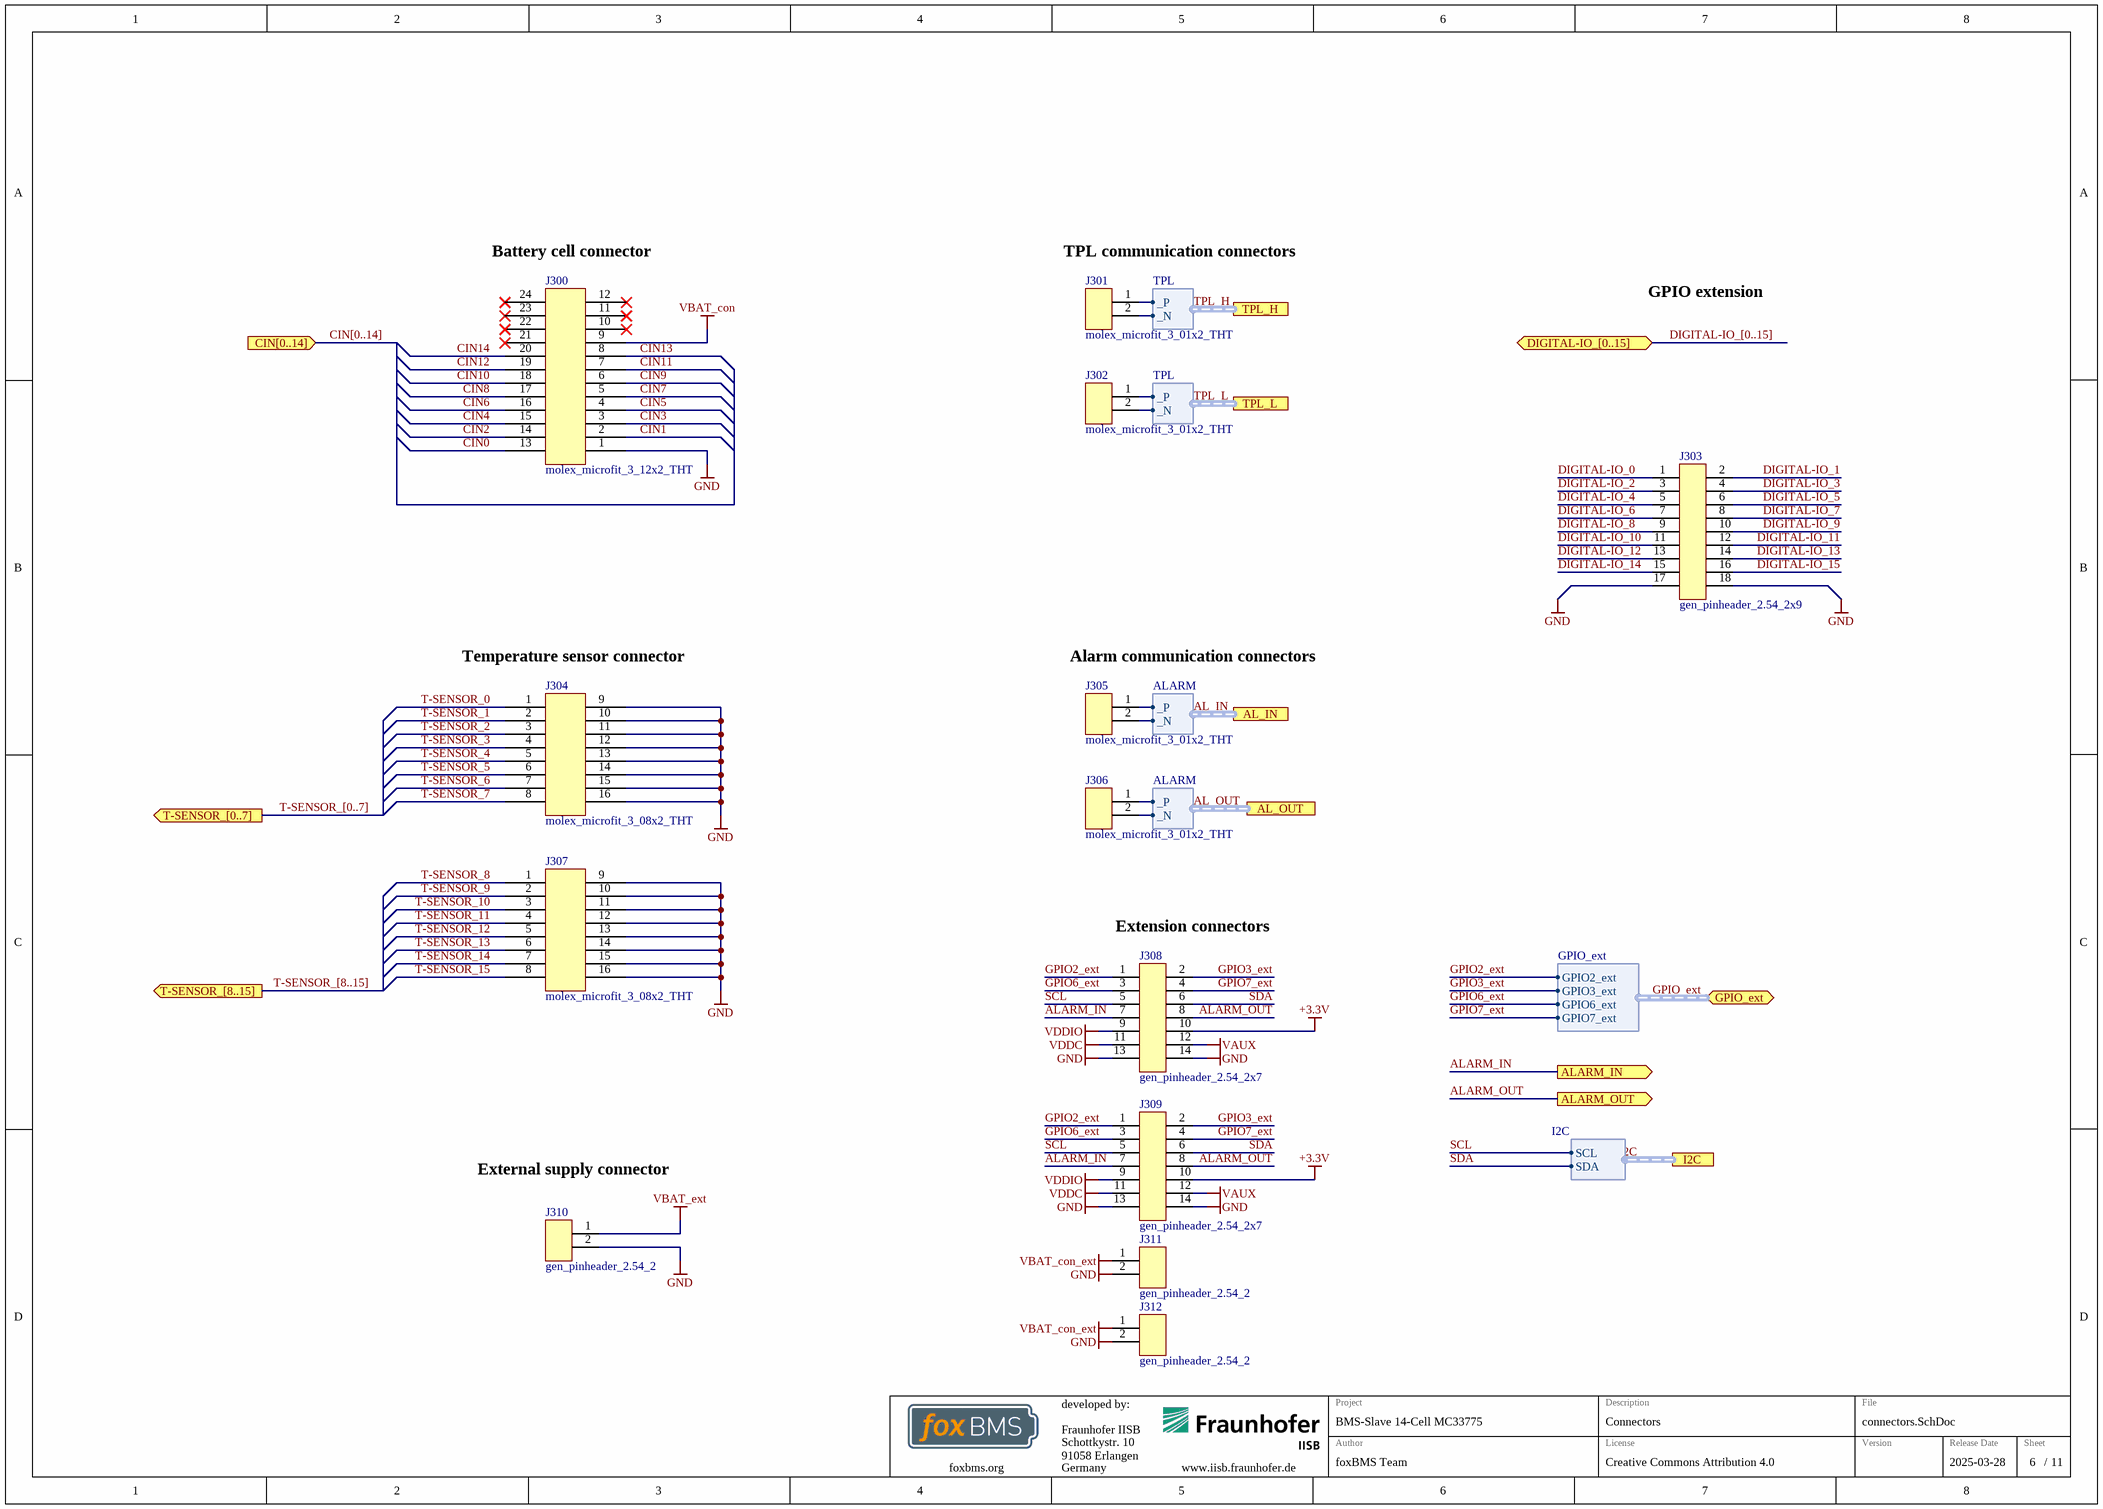
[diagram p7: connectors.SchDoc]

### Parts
J300  molex_microfit_3_12x2_THT  [MOLEX_MICROFIT_12x2_THT]
J301  molex_microfit_3_01x2_THT  [MOLEX_MICROFIT_01x2_THT]
J302  molex_microfit_3_01x2_THT  [MOLEX_MICROFIT_01x2_THT]
J303  gen_pinheader_2.54_2x9  [Pinheader_2.54_2x9]
J304  molex_microfit_3_08x2_THT  [MOLEX_MICROFIT_08x2_THT]
J305  molex_microfit_3_01x2_THT  [MOLEX_MICROFIT_01x2_THT]
J306  molex_microfit_3_01x2_THT  [MOLEX_MICROFIT_01x2_THT]
J307  molex_microfit_3_08x2_THT  [MOLEX_MICROFIT_08x2_THT]
J308  gen_pinheader_2.54_2x7  [Pinheader_2.54_2x7]
J309  gen_pinheader_2.54_2x7  [Pinheader_2.54_2x7]
J310  gen_pinheader_2.54_2  [Pinheader_2.54_2]
J311  gen_pinheader_2.54_2  [Pinheader_2.54_2]
J312  gen_pinheader_2.54_2  [Pinheader_2.54_2]

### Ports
AL_IN (harness ALARM), AL_OUT (harness ALARM), ALARM_IN (out), ALARM_OUT (out), CIN[0..14] (in), DIGITAL-IO_[0..15] (bidir), GPIO_ext (bidir, harness GPIO_ext), I2C (harness I2C), T-SENSOR_[0..7] (out), T-SENSOR_[8..15] (out), TPL_H (harness TPL), TPL_L (harness TPL)

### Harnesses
TPL: _P, _N
ALARM: _P, _N
GPIO_ext: GPIO3_ext, GPIO2_ext, GPIO6_ext, GPIO7_ext
I2C: SCL, SDA

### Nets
+3.3V: J308.10 J309.10
GND: J300.1 J303.17 J303.18 J304.9 J304.10 J304.11 J304.12 J304.13 J304.14 J304.15 J304.16 J307.9 J307.10 J307.11 J307.12 J307.13 J307.14 J307.15 J307.16 J308.13 J308.14 J309.13 J309.14 J310.2 J311.2 J312.2
VAUX: J308.12 J309.12
VBAT_con: J300.9
VBAT_con_ext: J311.1 J312.1
VBAT_ext: J310.1
VDDC: J308.11 J309.11
VDDIO: J308.9 J309.9
AL_IN._N: J305.2 ; port AL_IN._N
AL_IN._P: J305.1 ; port AL_IN._P
AL_OUT._N: J306.2 ; port AL_OUT._N
AL_OUT._P: J306.1 ; port AL_OUT._P
ALARM_IN: J308.7 J309.7 ; port ALARM_IN
ALARM_OUT: J308.8 J309.8 ; port ALARM_OUT
CIN0: J300.13
CIN1: J300.2  [project net BAL.CB_COM1]
CIN2: J300.14
CIN3: J300.3  [project net BAL.CB_COM3]
CIN4: J300.15
CIN5: J300.4  [project net BAL.CB_COM5]
CIN6: J300.16
CIN7: J300.5  [project net BAL.CB_COM7]
CIN8: J300.17
CIN9: J300.6  [project net BAL.CB_COM9]
CIN10: J300.18
CIN11: J300.7  [project net BAL.CB_COM11]
CIN12: J300.19
CIN13: J300.8  [project net BAL.CB_COM13]
CIN14: J300.20
DIGITAL-IO_0: J303.1
DIGITAL-IO_1: J303.2
DIGITAL-IO_2: J303.3
DIGITAL-IO_3: J303.4
DIGITAL-IO_4: J303.5
DIGITAL-IO_5: J303.6
DIGITAL-IO_6: J303.7
DIGITAL-IO_7: J303.8
DIGITAL-IO_8: J303.9
DIGITAL-IO_9: J303.10
DIGITAL-IO_10: J303.11
DIGITAL-IO_11: J303.12
DIGITAL-IO_12: J303.13
DIGITAL-IO_13: J303.14
DIGITAL-IO_14: J303.15
DIGITAL-IO_15: J303.16
GPIO2_ext: J308.1 J309.1 ; port GPIO_ext.GPIO2_ext
GPIO3_ext: J308.2 J309.2 ; port GPIO_ext.GPIO3_ext
GPIO6_ext: J308.3 J309.3 ; port GPIO_ext.GPIO6_ext
GPIO7_ext: J308.4 J309.4 ; port GPIO_ext.GPIO7_ext
SCL: J308.5 J309.5 ; port I2C.SCL  [project net I2C.SCL]
SDA: J308.6 J309.6 ; port I2C.SDA  [project net I2C.SDA]
T-SENSOR_0: J304.1
T-SENSOR_1: J304.2
T-SENSOR_2: J304.3
T-SENSOR_3: J304.4
T-SENSOR_4: J304.5
T-SENSOR_5: J304.6
T-SENSOR_6: J304.7
T-SENSOR_7: J304.8
T-SENSOR_8: J307.1  [project net T-SENSOR_0]
T-SENSOR_9: J307.2  [project net T-SENSOR_1]
T-SENSOR_10: J307.3
T-SENSOR_11: J307.4
T-SENSOR_12: J307.5
T-SENSOR_13: J307.6
T-SENSOR_14: J307.7
T-SENSOR_15: J307.8
TPL_H._N: J301.2 ; port TPL_H._N
TPL_H._P: J301.1 ; port TPL_H._P
TPL_L._N: J302.2 ; port TPL_L._N
TPL_L._P: J302.1 ; port TPL_L._P

Not connected (* = marked no-connect by the designer): J300 10* 11* 12* 21* 22* 23* 24*

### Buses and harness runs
bus CIN[0..14] = port CIN[0..14]
bus DIGITAL-IO_[0..15] = port DIGITAL-IO_[0..15]
bus T-SENSOR_[0..7] = port T-SENSOR_[0..7]
bus T-SENSOR_[8..15] = port T-SENSOR_[8..15]
harness AL_IN = port AL_IN
harness AL_OUT = port AL_OUT
harness GPIO_ext = port GPIO_ext
harness I2C = port I2C
harness TPL_H = port TPL_H
harness TPL_L = port TPL_L

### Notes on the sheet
- (near J300) Battery cell connector
- (near J301) TPL communication connectors
- GPIO extension
- (near J304) Temperature sensor connector
- (near J305) Alarm communication connectors
- (near J308) Extension connectors
- External supply connector

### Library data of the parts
J300 = molex_microfit_3_12x2_THT: Micro-Fit 3.0 Right Angle Header, 3.00mm Pitch, Dual Row, 24 Circuits, with Snap-in Plastic Peg PCB Lock, Tin, Glow Wire Capable, Black, 43045-2400; Manufacturer: Molex; Circuits: 24; Rated Voltage: 600V; Rated Current: 8.5A; Automotive Qualified: False
J301 J302 J305 J306 = molex_microfit_3_01x2_THT: Micro-Fit 3.0 Right Angle Header, 3.00mm Pitch, Dual Row, 2 Circuits, with Snap-in Plastic Peg PCB Lock, Tin, Glow Wire Capable, Black, 43045-0200; Manufacturer: Molex; Circuits: 2; Rated Voltage: 600V; Rated Current: 8.5A; Automotive Qualified: False
J303 = gen_pinheader_2.54_2x9: Standard Pinheader, THD, gerade, 2.54mm, 2-reihig; Circuits: 18; Rated Voltage: 250V; Rated Current: 3A; Automotive Qualified: False
J304 J307 = molex_microfit_3_08x2_THT: Micro-Fit 3.0 Right Angle Header, 3.00mm Pitch, Dual Row, 16 Circuits, with Snap-in Plastic Peg PCB Lock, Tin, Glow Wire Capable, Black, 43045-1600; Manufacturer: Molex; Circuits: 16; Rated Voltage: 600V; Rated Current: 8.5A; Automotive Qualified: False
J308 J309 = gen_pinheader_2.54_2x7: Standard Pinheader, THD, gerade, 2.54mm, 2-reihig; Circuits: 14; Rated Voltage: 250V; Rated Current: 3A; Automotive Qualified: False
J310-J312 = gen_pinheader_2.54_2: Standard Pinheader, THD, gerade, 2.54mm; Circuits: 2; Rated Voltage: 250V; Rated Current: 3A; Automotive Qualified: False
